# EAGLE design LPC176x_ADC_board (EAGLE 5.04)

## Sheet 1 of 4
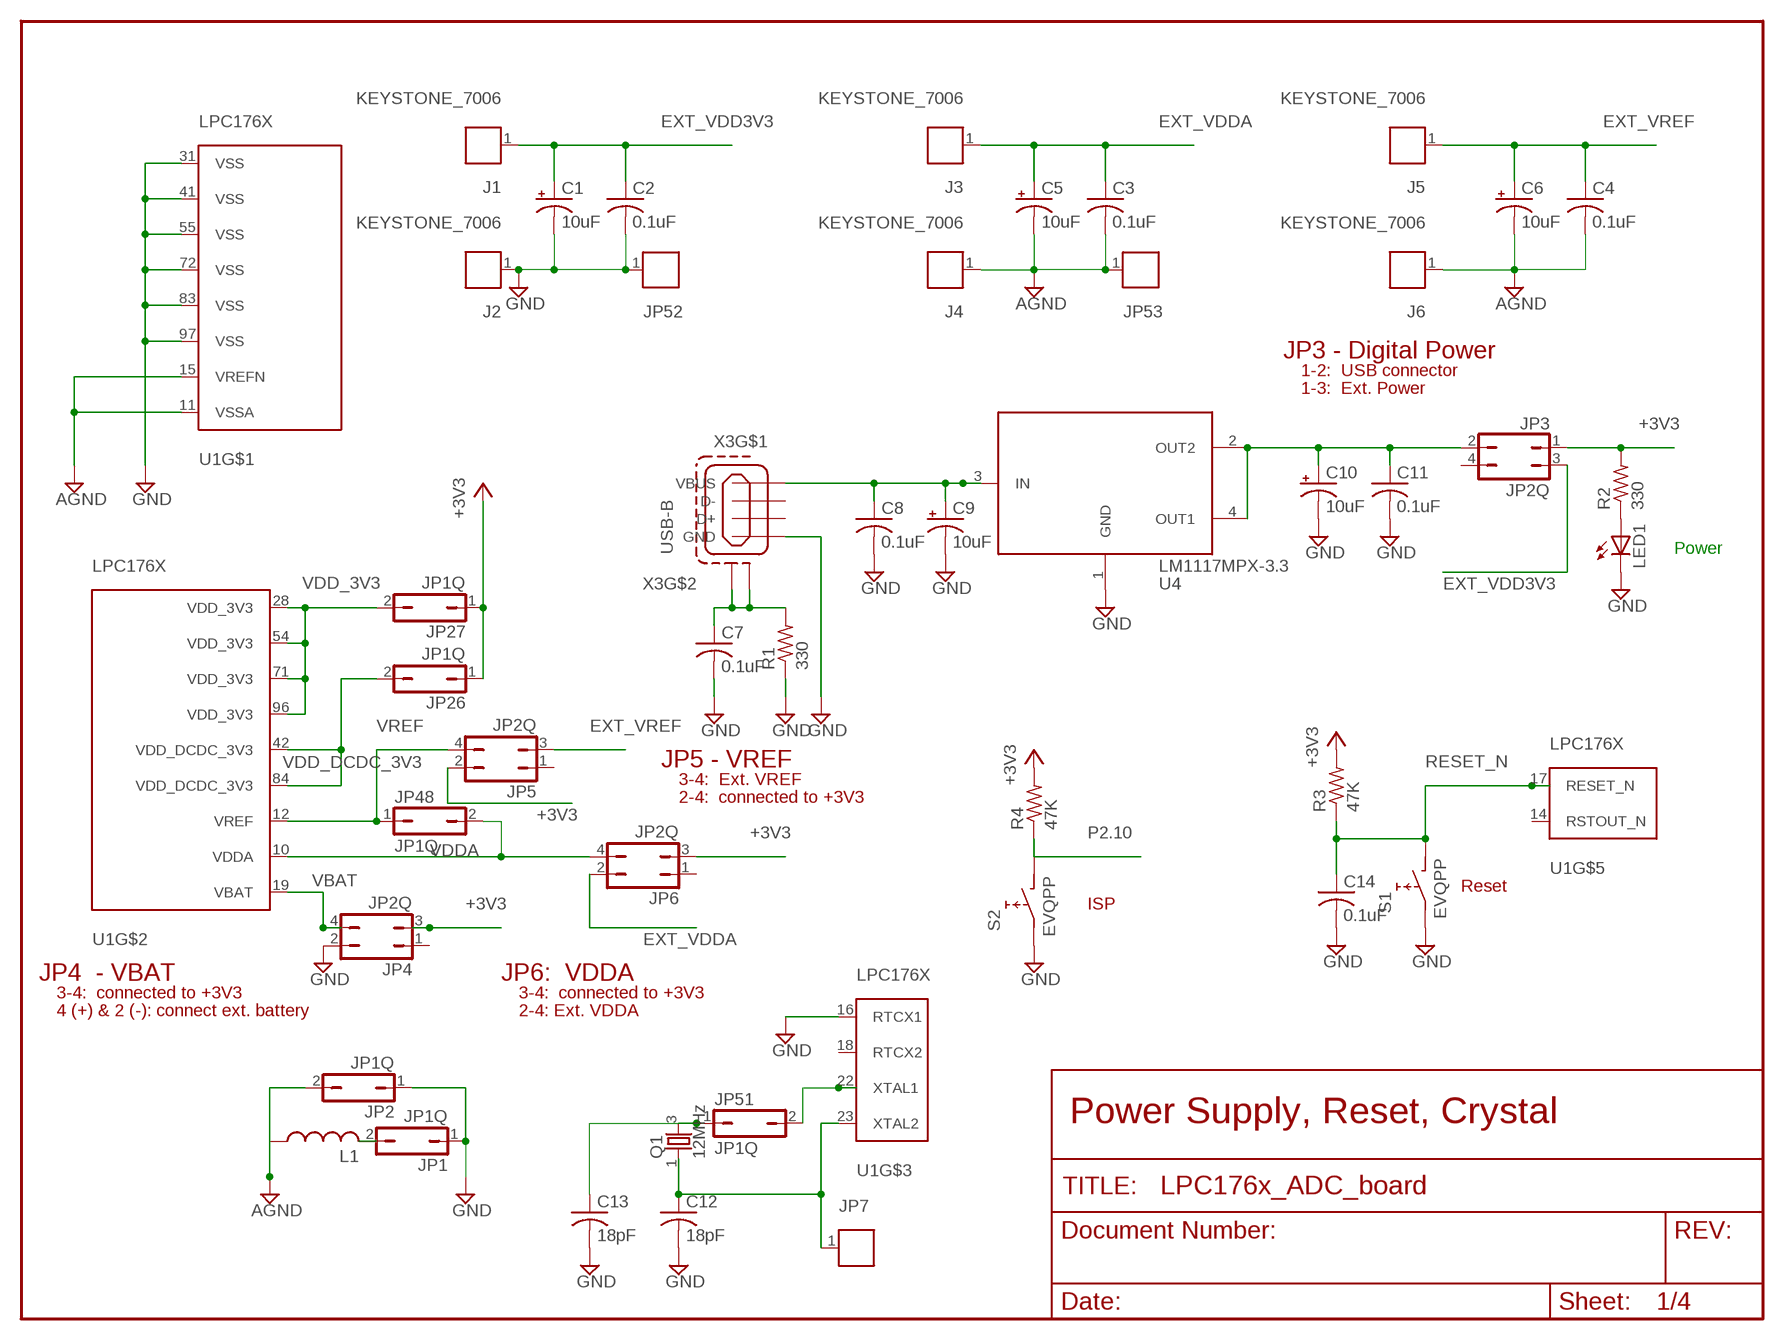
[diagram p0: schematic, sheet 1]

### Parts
C1  10uF  CPOL-USA/3216-18R  [A/3216-18R]
C2  0.1uF  C-USC0805  [C0805]
C3  0.1uF  C-USC0805  [C0805]
C4  0.1uF  C-USC0805  [C0805]
C5  10uF  CPOL-USA/3216-18R  [A/3216-18R]
C6  10uF  CPOL-USA/3216-18R  [A/3216-18R]
C7  0.1uF  C-USC0805  [C0805]
C8  0.1uF  C-USC0805  [C0805]
C9  10uF  CPOL-USA/3216-18R  [A/3216-18R]
C10  10uF  CPOL-USA/3216-18R  [A/3216-18R]
C11  0.1uF  C-USC0805  [C0805]
C12  18pF  C-USC0603  [C0603]
C13  18pF  C-USC0603  [C0603]
C14  0.1uF  C-USC0805  [C0805]
J1  KEYSTONE_7006  [KEYSTONE_7006]
J2  KEYSTONE_7006  [KEYSTONE_7006]
J3  KEYSTONE_7006  [KEYSTONE_7006]
J4  KEYSTONE_7006  [KEYSTONE_7006]
J5  KEYSTONE_7006  [KEYSTONE_7006]
J6  KEYSTONE_7006  [KEYSTONE_7006]
JP1  JP1Q  [JP1Q]
JP2  JP1Q  [JP1Q]
JP3  JP2Q  [JP2Q]
JP4  JP2Q  [JP2Q]
JP5  JP2Q  [JP2Q]
JP6  JP2Q  [JP2Q]
JP7  1PIN  [1PIN]
JP26  JP1Q  [JP1Q]
JP27  JP1Q  [JP1Q]
JP48  JP1Q  [JP1Q]
JP51  JP1Q  [JP1Q]
JP52  1PIN  [1PIN]
JP53  1PIN  [1PIN]
L1  L-US0207/15  [0207/15]
LED1  LEDCHIP-LED0603  [CHIP-LED0603]
Q1  12MHz  ABMM  [ABMM]
R1  330  R-US_R0805  [R0805]
R2  330  R-US_R0805  [R0805]
R3  47K  R-US_R0805  [R0805]
R4  47K  R-US_R0805  [R0805]
S1  EVQPP  [EVQPP]
S2  EVQPP  [EVQPP]
U1  LPC176X  [LQFP100_SOT407_1]
U4  LM1117MPX-3.3  [SOT223]
X3  USB-B  [USB-B-H]

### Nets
+3V3: JP3.1 JP4.3 JP5.2 JP6.3 JP26.1 JP27.1 R2.2 R3.2 R4.2 ; also sheet 2,3
AGND: C3.2 C4.2 C5.- C6.- J4.1 J6.1 JP2.2 JP53.1 L1.1 U1.11(VSSA) U1.15(VREFN) ; also sheet 2,3
EXT_VDD3V3: C1.+ C2.1 J1.1 JP3.3
EXT_VDDA: C3.1 C5.+ J3.1 JP6.2
EXT_VREF: C4.1 C6.+ J5.1 JP5.3
GND: C1.- C2.2 C7.2 C8.2 C9.- C10.- C11.2 C12.2 C13.2 C14.2 J2.1 JP1.1 JP2.1 JP4.2 JP52.1 LED1.C R1.1 S1.A S2.A U1.16(RTCX1) U1.31(VSS) U1.41(VSS) U1.55(VSS) U1.72(VSS) U1.83(VSS) U1.97(VSS) U4.1(GND) X3.GND ; also sheet 2,3
N$1: JP1.2 L1.2
N$2: C8.1 C9.+ U4.3(IN) X3.VBUS
N$3: LED1.A R2.1
N$4: C7.1 R1.2 X3.P$1(S1) X3.P$2(S2)
N$5: C10.+ C11.1 JP3.2 U4.2(OUT2) U4.4(OUT1)
N$10: C13.1 JP51.1 Q1.3
N$11: C12.1 JP7.1 Q1.1 U1.23(XTAL2)
N$20: JP51.2 U1.22(XTAL1)
P2.10: R4.1 S2.B ; also sheet 4
RESET_N: C14.1 R3.1 S1.B U1.17(RESET_N) ; also sheet 2
VBAT: JP4.4 U1.19(VBAT) ; also sheet 3
VDD_3V3: JP27.2 U1.28(VDD_3V3) U1.54(VDD_3V3) U1.71(VDD_3V3) U1.96(VDD_3V3) ; also sheet 3
VDD_DCDC_3V3: JP26.2 U1.42(VDD_DCDC_3V3) U1.84(VDD_DCDC_3V3) ; also sheet 3
VDDA: JP6.4 JP48.2 U1.10(VDDA) ; also sheet 3
VREF: JP5.4 JP48.1 U1.12(VREF) ; also sheet 2,3
Unconnected: JP3.4 JP4.1 JP5.1 JP6.1 U1.14(RSTOUT_N) U1.18(RTCX2) X3.D+ X3.D-

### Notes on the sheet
- JP3 - Digital Power
- 1-2:  USB connector
- 1-3:  Ext. Power
- Power
- JP5 - VREF
- 3-4:  Ext. VREF
- 2-4:  connected to +3V3
- Reset
- ISP
- JP4  - VBAT | JP6:  VDDA
- 3-4:  connected to +3V3 | 3-4:  connected to +3V3
- 4 (+) & 2 (-): connect ext. battery | 2-4: Ext. VDDA
- Power Supply, Reset, Crystal

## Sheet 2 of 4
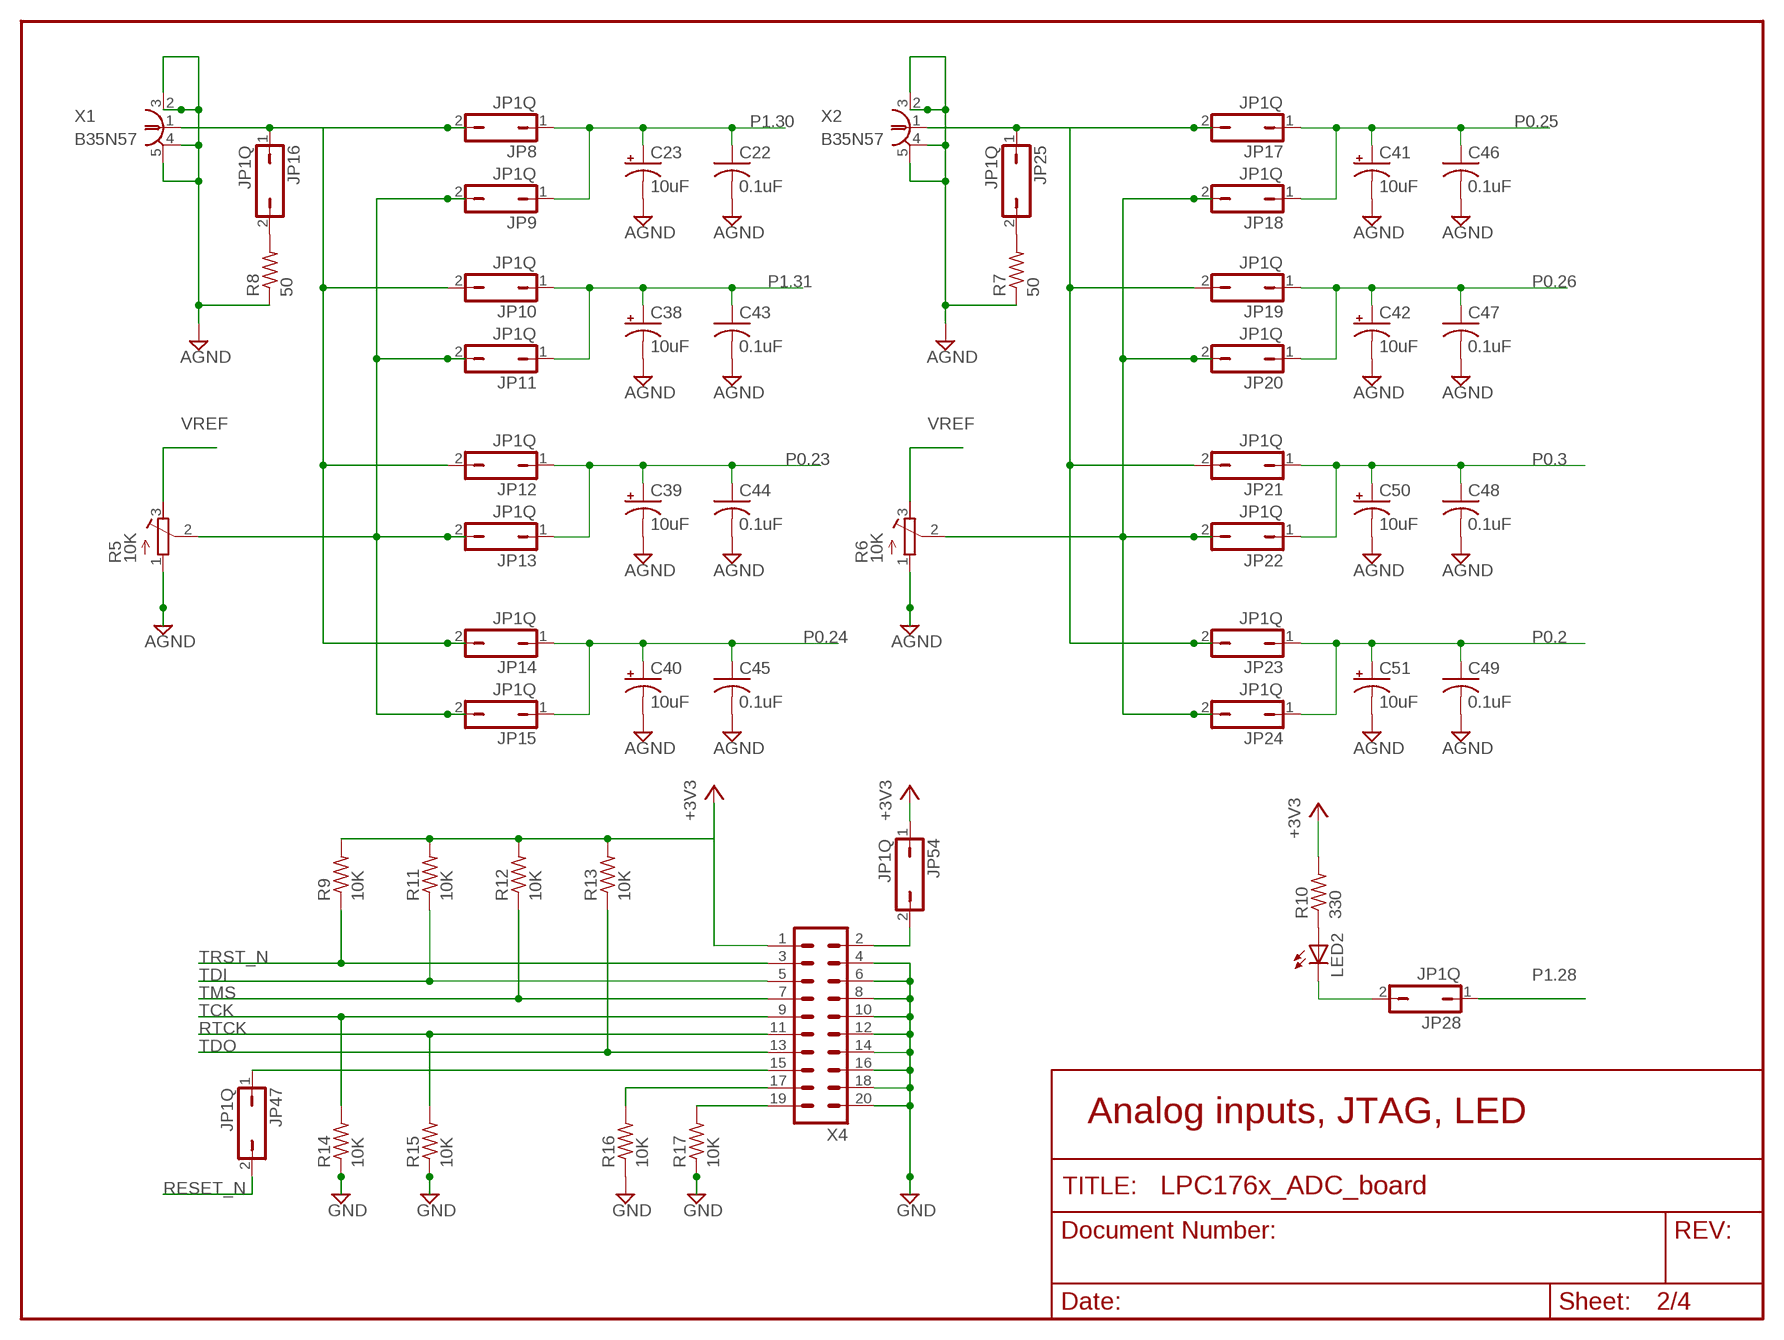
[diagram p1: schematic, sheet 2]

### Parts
C22  0.1uF  C-USC0402  [C0402]
C23  10uF  CPOL-USA/3216-18R  [A/3216-18R]
C38  10uF  CPOL-USA/3216-18R  [A/3216-18R]
C39  10uF  CPOL-USA/3216-18R  [A/3216-18R]
C40  10uF  CPOL-USA/3216-18R  [A/3216-18R]
C41  10uF  CPOL-USCT3216  [CT3216]
C42  10uF  CPOL-USCT3216  [CT3216]
C43  0.1uF  C-USC0402  [C0402]
C44  0.1uF  C-USC0402  [C0402]
C45  0.1uF  C-USC0402  [C0402]
C46  0.1uF  C-USC0402  [C0402]
C47  0.1uF  C-USC0402  [C0402]
C48  0.1uF  C-USC0402  [C0402]
C49  0.1uF  C-USC0402  [C0402]
C50  10uF  CPOL-USCT3216  [CT3216]
C51  10uF  CPOL-USCT3216  [CT3216]
JP8  JP1Q  [JP1Q]
JP9  JP1Q  [JP1Q]
JP10  JP1Q  [JP1Q]
JP11  JP1Q  [JP1Q]
JP12  JP1Q  [JP1Q]
JP13  JP1Q  [JP1Q]
JP14  JP1Q  [JP1Q]
JP15  JP1Q  [JP1Q]
JP16  JP1Q  [JP1Q]
JP17  JP1Q  [JP1Q]
JP18  JP1Q  [JP1Q]
JP19  JP1Q  [JP1Q]
JP20  JP1Q  [JP1Q]
JP21  JP1Q  [JP1Q]
JP22  JP1Q  [JP1Q]
JP23  JP1Q  [JP1Q]
JP24  JP1Q  [JP1Q]
JP25  JP1Q  [JP1Q]
JP28  JP1Q  [JP1Q]
JP47  JP1Q  [JP1Q]
JP54  JP1Q  [JP1Q]
LED2  LEDCHIP-LED0603  [CHIP-LED0603]
R5  10K  3224W3224W  [RTRIM3224W]
R6  10K  3224W3224W  [RTRIM3224W]
R7  50  R-US_R0805  [R0805]
R8  50  R-US_R0805  [R0805]
R9  10K  R-US_R0805  [R0805]
R10  330  R-US_R0805  [R0805]
R11  10K  R-US_R0805  [R0805]
R12  10K  R-US_R0805  [R0805]
R13  10K  R-US_R0805  [R0805]
R14  10K  R-US_R0805  [R0805]
R15  10K  R-US_R0805  [R0805]
R16  10K  R-US_R0805  [R0805]
R17  10K  R-US_R0805  [R0805]
X1  B35N57  [B35N57]
X2  B35N57  [B35N57]
X4  MA10-2  [MA10-2]

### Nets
+3V3: JP54.1 R9.2 R10.2 R11.2 R12.2 R13.2 X4.1 ; also sheet 1,3
AGND: C22.2 C23.- C38.- C39.- C40.- C41.- C42.- C43.2 C44.2 C45.2 C46.2 C47.2 C48.2 C49.2 C50.- C51.- R5.1(E) R6.1(E) R7.1 R8.1 X1.2 X1.3 X1.4 X1.5 X2.2 X2.3 X2.4 X2.5 ; also sheet 1,3
GND: R14.1 R15.1 R16.1 R17.1 X4.4 X4.6 X4.8 X4.10 X4.12 X4.14 X4.16 X4.18 X4.20 ; also sheet 1,3
N$7: JP16.2 R8.2
N$8: JP54.2 X4.2
N$9: JP9.2 JP11.2 JP13.2 JP15.2 R5.2(S)
N$12: R17.2 X4.19
N$13: JP8.2 JP10.2 JP12.2 JP14.2 JP16.1 X1.1
N$14: JP18.2 JP20.2 JP22.2 JP24.2 R6.2(S)
N$15: JP17.2 JP19.2 JP21.2 JP23.2 JP25.1 X2.1
N$16: JP25.2 R7.2
N$18: LED2.A R10.1
N$22: R16.2 X4.17
N$24: JP47.1 X4.15
N$51: JP28.2 LED2.C
P0.2: C49.1 C51.+ JP23.1 JP24.1 ; also sheet 3,4
P0.3: C48.1 C50.+ JP21.1 JP22.1 ; also sheet 3,4
P0.23: C39.+ C44.1 JP12.1 JP13.1 ; also sheet 4
P0.24: C40.+ C45.1 JP14.1 JP15.1 ; also sheet 4
P0.25: C41.+ C46.1 JP17.1 JP18.1 ; also sheet 4
P0.26: C42.+ C47.1 JP19.1 JP20.1 ; also sheet 4
P1.28: JP28.1 ; also sheet 4
P1.30: C22.1 C23.+ JP8.1 JP9.1 ; also sheet 4
P1.31: C38.+ C43.1 JP10.1 JP11.1 ; also sheet 4
RESET_N: JP47.2 ; also sheet 1
RTCK: R15.2 X4.11 ; also sheet 3
TCK: R14.2 X4.9 ; also sheet 3
TDI: R11.1 X4.5 ; also sheet 3
TDO: R13.1 X4.13 ; also sheet 3
TMS: R12.1 X4.7 ; also sheet 3
TRST_N: R9.1 X4.3 ; also sheet 3
VREF: R5.3(A) R6.3(A) ; also sheet 1,3

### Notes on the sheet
- Analog inputs, JTAG, LED

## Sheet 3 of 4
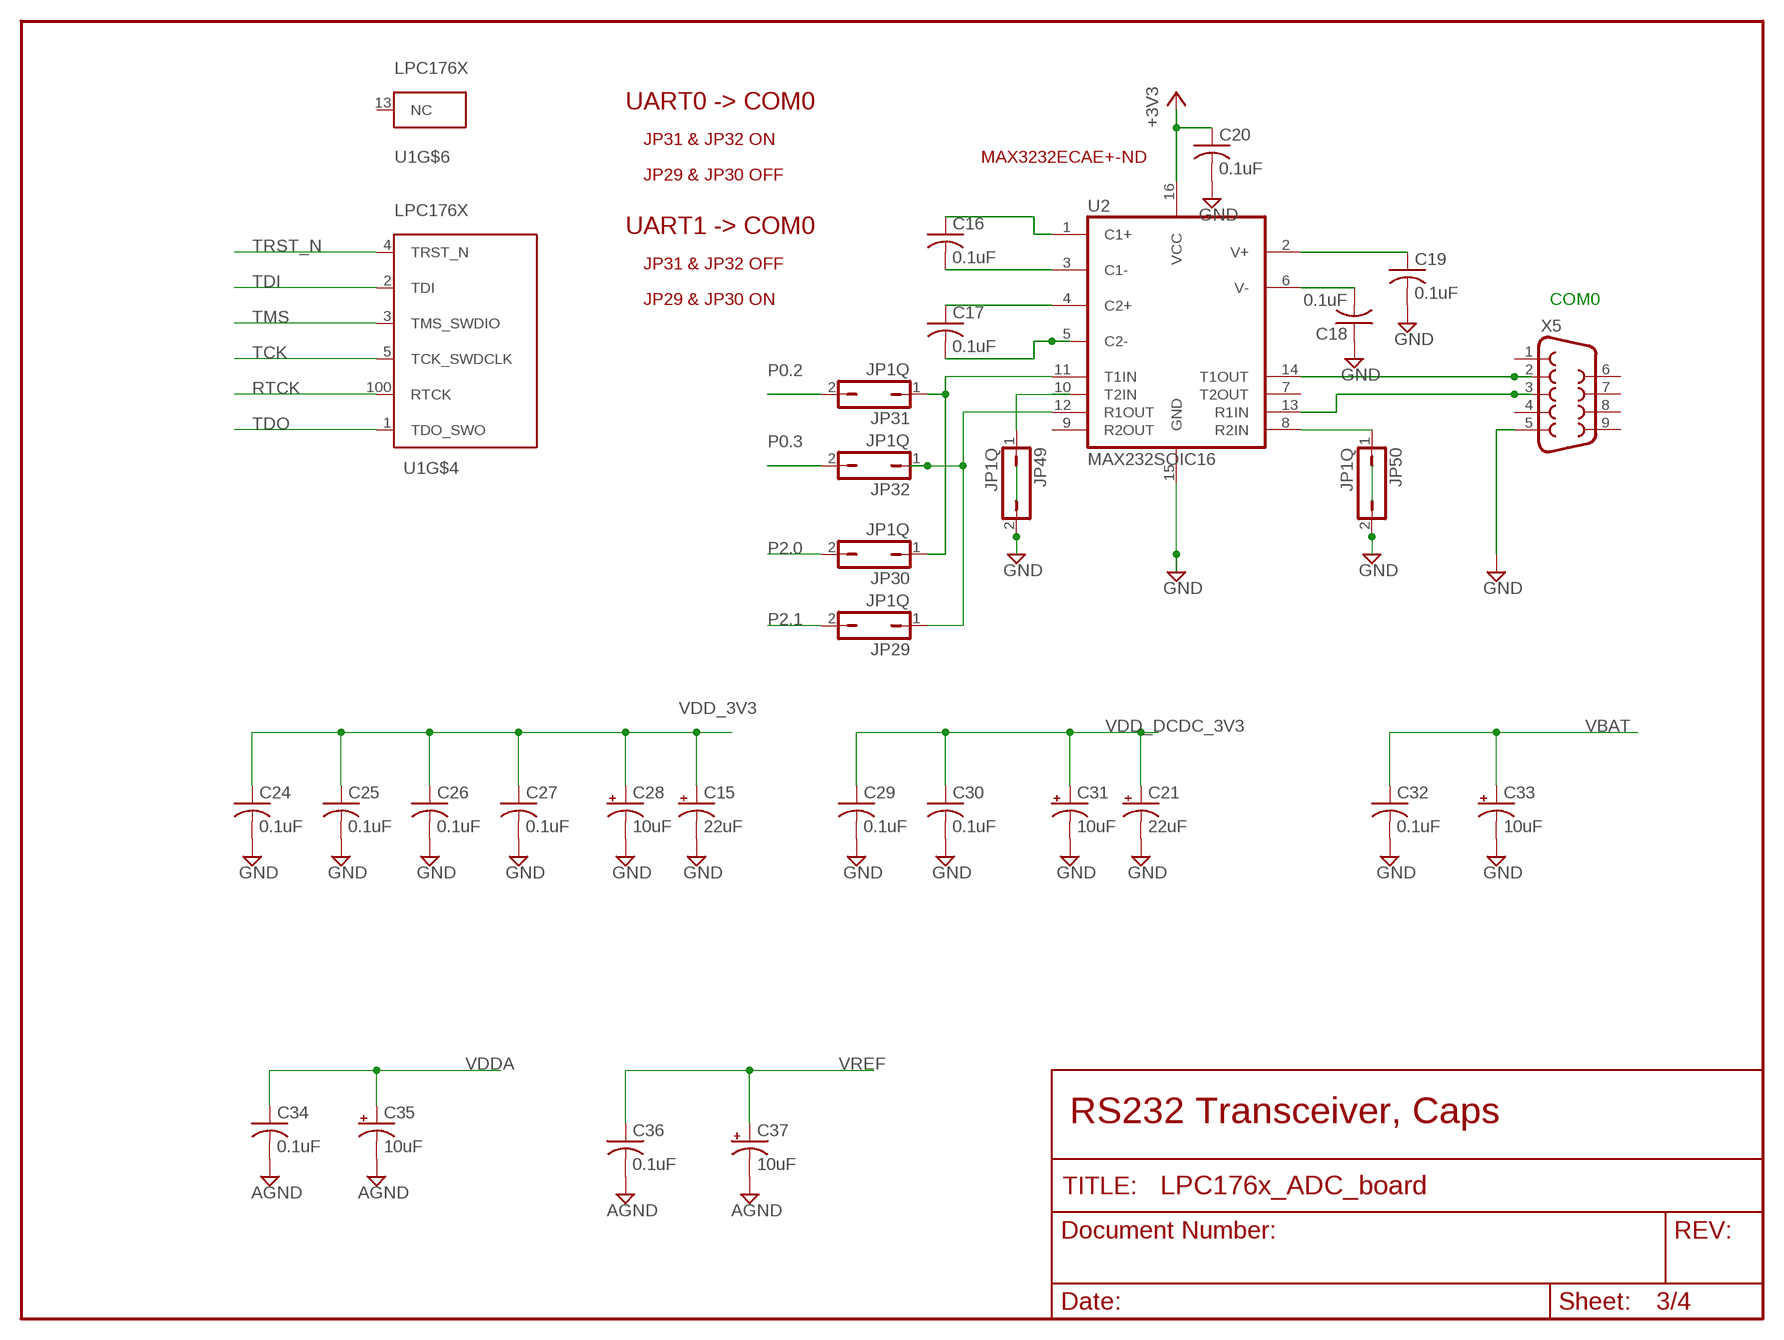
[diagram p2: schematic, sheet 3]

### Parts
C15  22uF  CPOL-USA/3216-18R  [A/3216-18R]
C16  0.1uF  C-USC0805  [C0805]
C17  0.1uF  C-USC0805  [C0805]
C18  0.1uF  C-USC0805  [C0805]
C19  0.1uF  C-USC0805  [C0805]
C20  0.1uF  C-USC0805  [C0805]
C21  22uF  CPOL-USA/3216-18R  [A/3216-18R]
C24  0.1uF  C-USC0402  [C0402]
C25  0.1uF  C-USC0402  [C0402]
C26  0.1uF  C-USC0402  [C0402]
C27  0.1uF  C-USC0402  [C0402]
C28  10uF  CPOL-USA/3216-18R  [A/3216-18R]
C29  0.1uF  C-USC0402  [C0402]
C30  0.1uF  C-USC0402  [C0402]
C31  10uF  CPOL-USA/3216-18R  [A/3216-18R]
C32  0.1uF  C-USC0402  [C0402]
C33  10uF  CPOL-USA/3216-18R  [A/3216-18R]
C34  0.1uF  C-USC0402  [C0402]
C35  10uF  CPOL-USA/3216-18R  [A/3216-18R]
C36  0.1uF  C-USC0402  [C0402]
C37  10uF  CPOL-USA/3216-18R  [A/3216-18R]
JP29  JP1Q  [JP1Q]
JP30  JP1Q  [JP1Q]
JP31  JP1Q  [JP1Q]
JP32  JP1Q  [JP1Q]
JP49  JP1Q  [JP1Q]
JP50  JP1Q  [JP1Q]
U2  MAX232SOIC16  [SO016]
X5  DB9  [DB9]

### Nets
+3V3: C20.1 U2.16(VCC) ; also sheet 1,2
AGND: C34.2 C35.- C36.2 C37.- ; also sheet 1,2
GND: C15.- C18.1 C19.2 C20.2 C21.- C24.2 C25.2 C26.2 C27.2 C28.- C29.2 C30.2 C31.- C32.2 C33.- JP49.2 JP50.2 U2.15(GND) X5.5 ; also sheet 1,2
N$6: JP30.1 JP31.1 U2.11(T1IN)
N$23: C18.2 U2.6(V-)
N$25: C19.1 U2.2(V+)
N$26: C16.1 U2.1(C1+)
N$27: C16.2 U2.3(C1-)
N$28: C17.1 U2.4(C2+)
N$29: C17.2 U2.5(C2-)
N$30: JP29.1 JP32.1 U2.12(R1OUT)
N$31: JP49.1 U2.10(T2IN)
N$32: JP50.1 U2.8(R2IN)
N$35: U2.14(T1OUT) X5.2
N$36: U2.13(R1IN) X5.3
P0.2: JP31.2 ; also sheet 2,4
P0.3: JP32.2 ; also sheet 2,4
P2.0: JP30.2 ; also sheet 4
P2.1: JP29.2 ; also sheet 4
RTCK: U1.100(RTCK) ; also sheet 2
TCK: U1.5(TCK_SWDCLK) ; also sheet 2
TDI: U1.2(TDI) ; also sheet 2
TDO: U1.1(TDO_SWO) ; also sheet 2
TMS: U1.3(TMS_SWDIO) ; also sheet 2
TRST_N: U1.4(TRST_N) ; also sheet 2
VBAT: C32.1 C33.+ ; also sheet 1
VDD_3V3: C15.+ C24.1 C25.1 C26.1 C27.1 C28.+ ; also sheet 1
VDD_DCDC_3V3: C21.+ C29.1 C30.1 C31.+ ; also sheet 1
VDDA: C34.1 C35.+ ; also sheet 1
VREF: C36.1 C37.+ ; also sheet 1,2
Unconnected: U1.13(NC) U2.7(T2OUT) U2.9(R2OUT) X5.1 X5.4 X5.6 X5.7 X5.8 X5.9

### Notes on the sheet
- UART0 -> COM0
- JP31 & JP32 ON
- MAX3232ECAE+-ND
- JP29 & JP30 OFF
- UART1 -> COM0
- JP31 & JP32 OFF
- JP29 & JP30 ON | COM0
- RS232 Transceiver, Caps

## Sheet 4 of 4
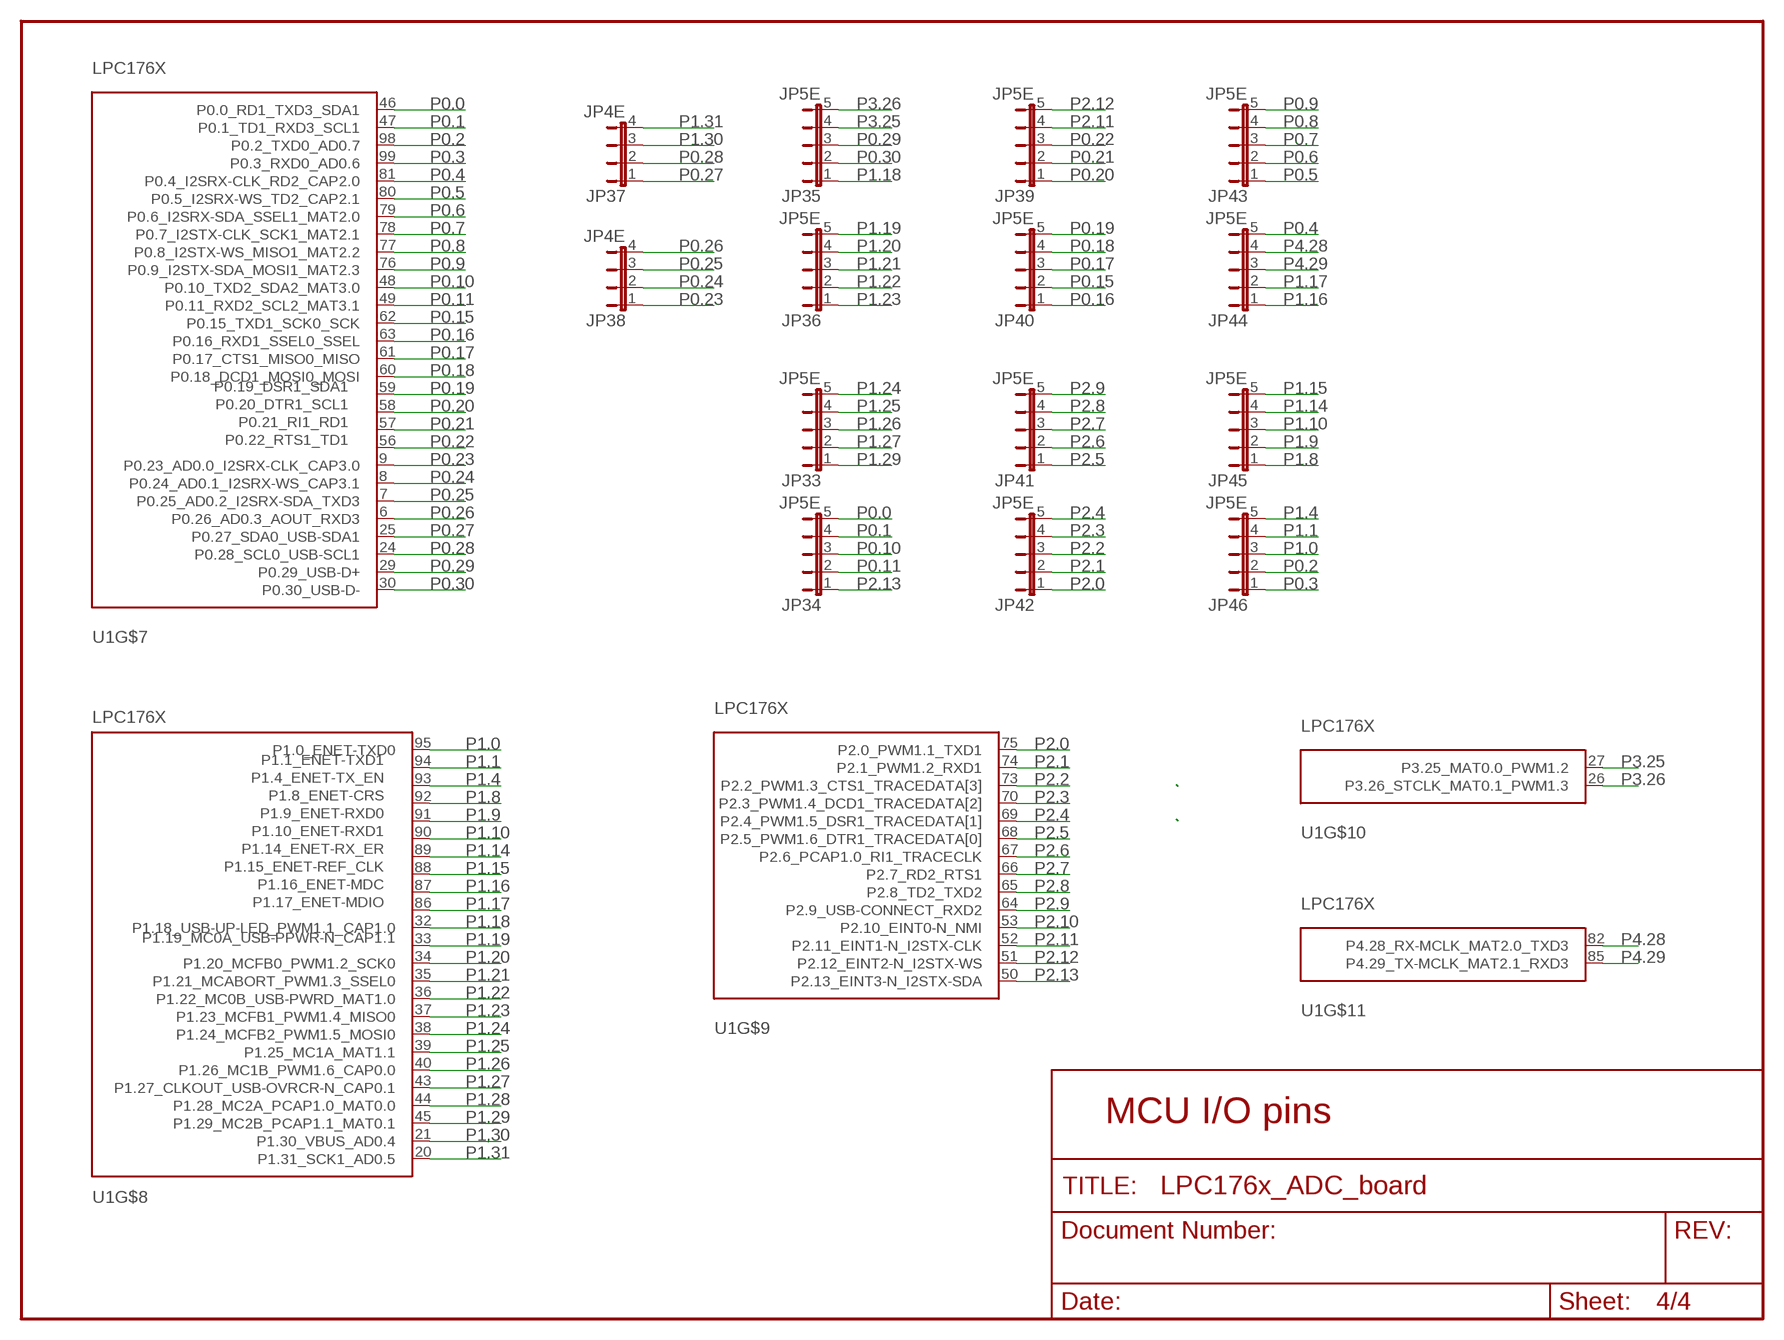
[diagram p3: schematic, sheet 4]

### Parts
JP33  JP5E  [JP5E]
JP34  JP5E  [JP5E]
JP35  JP5E  [JP5E]
JP36  JP5E  [JP5E]
JP37  JP4E  [JP4E]
JP38  JP4E  [JP4E]
JP39  JP5E  [JP5E]
JP40  JP5E  [JP5E]
JP41  JP5E  [JP5E]
JP42  JP5E  [JP5E]
JP43  JP5E  [JP5E]
JP44  JP5E  [JP5E]
JP45  JP5E  [JP5E]
JP46  JP5E  [JP5E]

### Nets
P0.0: JP34.5 U1.46(P0.0_RD1_TXD3_SDA1)
P0.1: JP34.4 U1.47(P0.1_TD1_RXD3_SCL1)
P0.2: JP46.2 U1.98(P0.2_TXD0_AD0.7) ; also sheet 2,3
P0.3: JP46.1 U1.99(P0.3_RXD0_AD0.6) ; also sheet 2,3
P0.4: JP44.5 U1.81(P0.4_I2SRX-CLK_RD2_CAP2.0)
P0.5: JP43.1 U1.80(P0.5_I2SRX-WS_TD2_CAP2.1)
P0.6: JP43.2 U1.79(P0.6_I2SRX-SDA_SSEL1_MAT2.0)
P0.7: JP43.3 U1.78(P0.7_I2STX-CLK_SCK1_MAT2.1)
P0.8: JP43.4 U1.77(P0.8_I2STX-WS_MISO1_MAT2.2)
P0.9: JP43.5 U1.76(P0.9_I2STX-SDA_MOSI1_MAT2.3)
P0.10: JP34.3 U1.48(P0.10_TXD2_SDA2_MAT3.0)
P0.11: JP34.2 U1.49(P0.11_RXD2_SCL2_MAT3.1)
P0.15: JP40.2 U1.62(P0.15_TXD1_SCK0_SCK)
P0.16: JP40.1 U1.63(P0.16_RXD1_SSEL0_SSEL)
P0.17: JP40.3 U1.61(P0.17_CTS1_MISO0_MISO)
P0.18: JP40.4 U1.60(P0.18_DCD1_MOSI0_MOSI)
P0.19: JP40.5 U1.59(P0.19_DSR1_SDA1
)
P0.20: JP39.1 U1.58(P0.20_DTR1_SCL1
)
P0.21: JP39.2 U1.57(P0.21_RI1_RD1
)
P0.22: JP39.3 U1.56(P0.22_RTS1_TD1
)
P0.23: JP38.1 U1.9(P0.23_AD0.0_I2SRX-CLK_CAP3.0) ; also sheet 2
P0.24: JP38.2 U1.8(P0.24_AD0.1_I2SRX-WS_CAP3.1) ; also sheet 2
P0.25: JP38.3 U1.7(P0.25_AD0.2_I2SRX-SDA_TXD3) ; also sheet 2
P0.26: JP38.4 U1.6(P0.26_AD0.3_AOUT_RXD3) ; also sheet 2
P0.27: JP37.1 U1.25(P0.27_SDA0_USB-SDA1)
P0.28: JP37.2 U1.24(P0.28_SCL0_USB-SCL1)
P0.29: JP35.3 U1.29(P0.29_USB-D+)
P0.30: JP35.2 U1.30(P0.30_USB-D-)
P1.0: JP46.3 U1.95(P1.0_ENET-TXD0)
P1.1: JP46.4 U1.94(P1.1_ENET-TXD1
)
P1.4: JP46.5 U1.93(P1.4_ENET-TX_EN
)
P1.8: JP45.1 U1.92(P1.8_ENET-CRS
)
P1.9: JP45.2 U1.91(P1.9_ENET-RXD0
)
P1.10: JP45.3 U1.90(P1.10_ENET-RXD1
)
P1.14: JP45.4 U1.89(P1.14_ENET-RX_ER
)
P1.15: JP45.5 U1.88(P1.15_ENET-REF_CLK
)
P1.16: JP44.1 U1.87(P1.16_ENET-MDC
)
P1.17: JP44.2 U1.86(P1.17_ENET-MDIO
)
P1.18: JP35.1 U1.32(P1.18_USB-UP-LED_PWM1.1_CAP1.0)
P1.19: JP36.5 U1.33(P1.19_MC0A_USB-PPWR-N_CAP1.1
)
P1.20: JP36.4 U1.34(P1.20_MCFB0_PWM1.2_SCK0)
P1.21: JP36.3 U1.35(P1.21_MCABORT_PWM1.3_SSEL0)
P1.22: JP36.2 U1.36(P1.22_MC0B_USB-PWRD_MAT1.0)
P1.23: JP36.1 U1.37(P1.23_MCFB1_PWM1.4_MISO0)
P1.24: JP33.5 U1.38(P1.24_MCFB2_PWM1.5_MOSI0)
P1.25: JP33.4 U1.39(P1.25_MC1A_MAT1.1)
P1.26: JP33.3 U1.40(P1.26_MC1B_PWM1.6_CAP0.0)
P1.27: JP33.2 U1.43(P1.27_CLKOUT_USB-OVRCR-N_CAP0.1)
P1.28: U1.44(P1.28_MC2A_PCAP1.0_MAT0.0) ; also sheet 2
P1.29: JP33.1 U1.45(P1.29_MC2B_PCAP1.1_MAT0.1)
P1.30: JP37.3 U1.21(P1.30_VBUS_AD0.4) ; also sheet 2
P1.31: JP37.4 U1.20(P1.31_SCK1_AD0.5) ; also sheet 2
P2.0: JP42.1 U1.75(P2.0_PWM1.1_TXD1) ; also sheet 3
P2.1: JP42.2 U1.74(P2.1_PWM1.2_RXD1) ; also sheet 3
P2.2: JP42.3 U1.73(P2.2_PWM1.3_CTS1_TRACEDATA[3])
P2.3: JP42.4 U1.70(P2.3_PWM1.4_DCD1_TRACEDATA[2])
P2.4: JP42.5 U1.69(P2.4_PWM1.5_DSR1_TRACEDATA[1])
P2.5: JP41.1 U1.68(P2.5_PWM1.6_DTR1_TRACEDATA[0])
P2.6: JP41.2 U1.67(P2.6_PCAP1.0_RI1_TRACECLK)
P2.7: JP41.3 U1.66(P2.7_RD2_RTS1)
P2.8: JP41.4 U1.65(P2.8_TD2_TXD2)
P2.9: JP41.5 U1.64(P2.9_USB-CONNECT_RXD2)
P2.10: U1.53(P2.10_EINT0-N_NMI) ; also sheet 1
P2.11: JP39.4 U1.52(P2.11_EINT1-N_I2STX-CLK)
P2.12: JP39.5 U1.51(P2.12_EINT2-N_I2STX-WS)
P2.13: JP34.1 U1.50(P2.13_EINT3-N_I2STX-SDA)
P3.25: JP35.4 U1.27(P3.25_MAT0.0_PWM1.2)
P3.26: JP35.5 U1.26(P3.26_STCLK_MAT0.1_PWM1.3)
P4.28: JP44.4 U1.82(P4.28_RX-MCLK_MAT2.0_TXD3)
P4.29: JP44.3 U1.85(P4.29_TX-MCLK_MAT2.1_RXD3)

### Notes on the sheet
- MCU I/O pins

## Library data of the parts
C1 C5 C6 C9 C10 C15 C21 C23 C28 C31 C33 C35 C37-C42 C50 C51 = rcl:CPOL-US: POLARIZED CAPACITOR, American symbol
C2-C4 C7 C8 C11-C14 C16-C20 C22 C24-C27 C29 C30 C32 C34 C36 C43-C49 = rcl:C-US: CAPACITOR, American symbol
J1-J6 = Chun:KEYSTONE_7006
JP1 JP2 JP8-JP32 JP47-JP51 JP54 = Chun:JP1Q
JP3-JP6 = Chun:JP2Q
JP7 JP52 JP53 = Chun:1PIN
JP33-JP36 JP39-JP46 = Chun:JP5E
JP37 JP38 = Chun:JP4E
L1 = rcl:L-US: INDUCTOR, American symbol
LED1 LED2 = led:LED: LED
Q1 = Chun:ABMM
R1-R4 R7-R17 = rcl:R-US_: RESISTOR, American symbol
R5 R6 = Chun:3224W: Trimm resistor
S1 S2 = Chun:EVQPP
U1 = Chun:LPC176X
U2 = SparkFun:MAX232: RS232 Transceiver Very common IC. This is generically called 'MAX232', but works with the 3V equivalent MAX3232 generic ICs. Field tested and mother approved. Spark Fun Electronics SKU : COM-00316 (DIP) and COM-00589 (SMD)
U4 = Chun:LM1117MPX-3.3
X1 X2 = Chun:B35N57
X3 = Chun:USB-B
X4 = con-lstb:MA10-2: PIN HEADER
X5 = SparkFun:DB9: DB9 Connector Standard DB9 (D-Sub 9) serial connector. Can be used for CAN bus as well as RS485 and RS232. Footprint production proven. Spark Fun Electronics SKU : PRT-00429

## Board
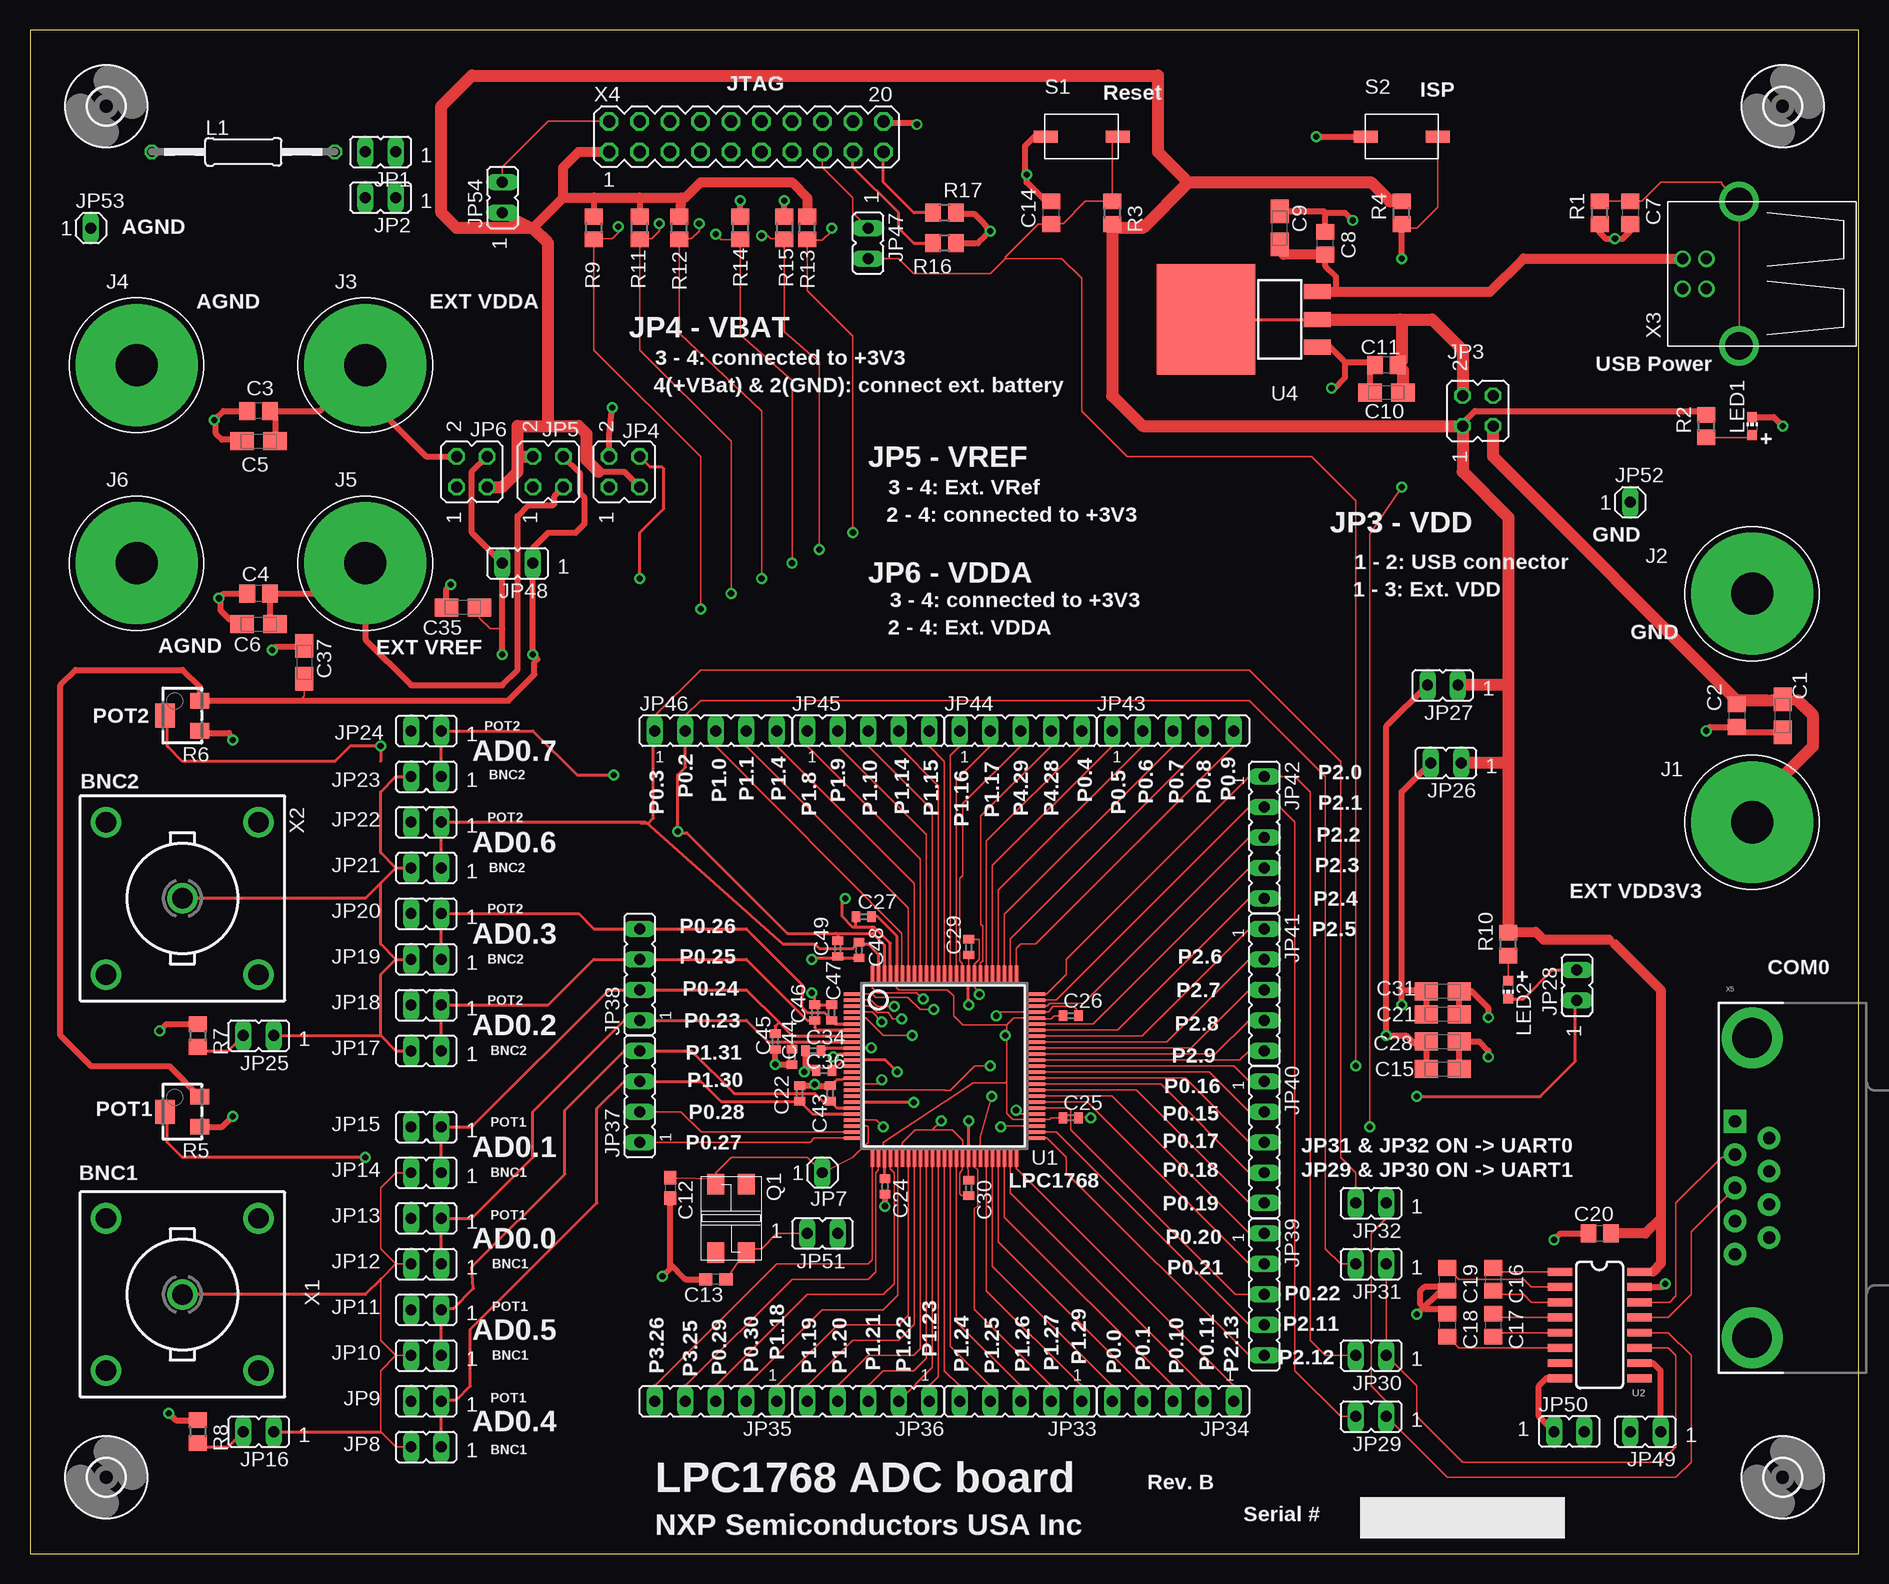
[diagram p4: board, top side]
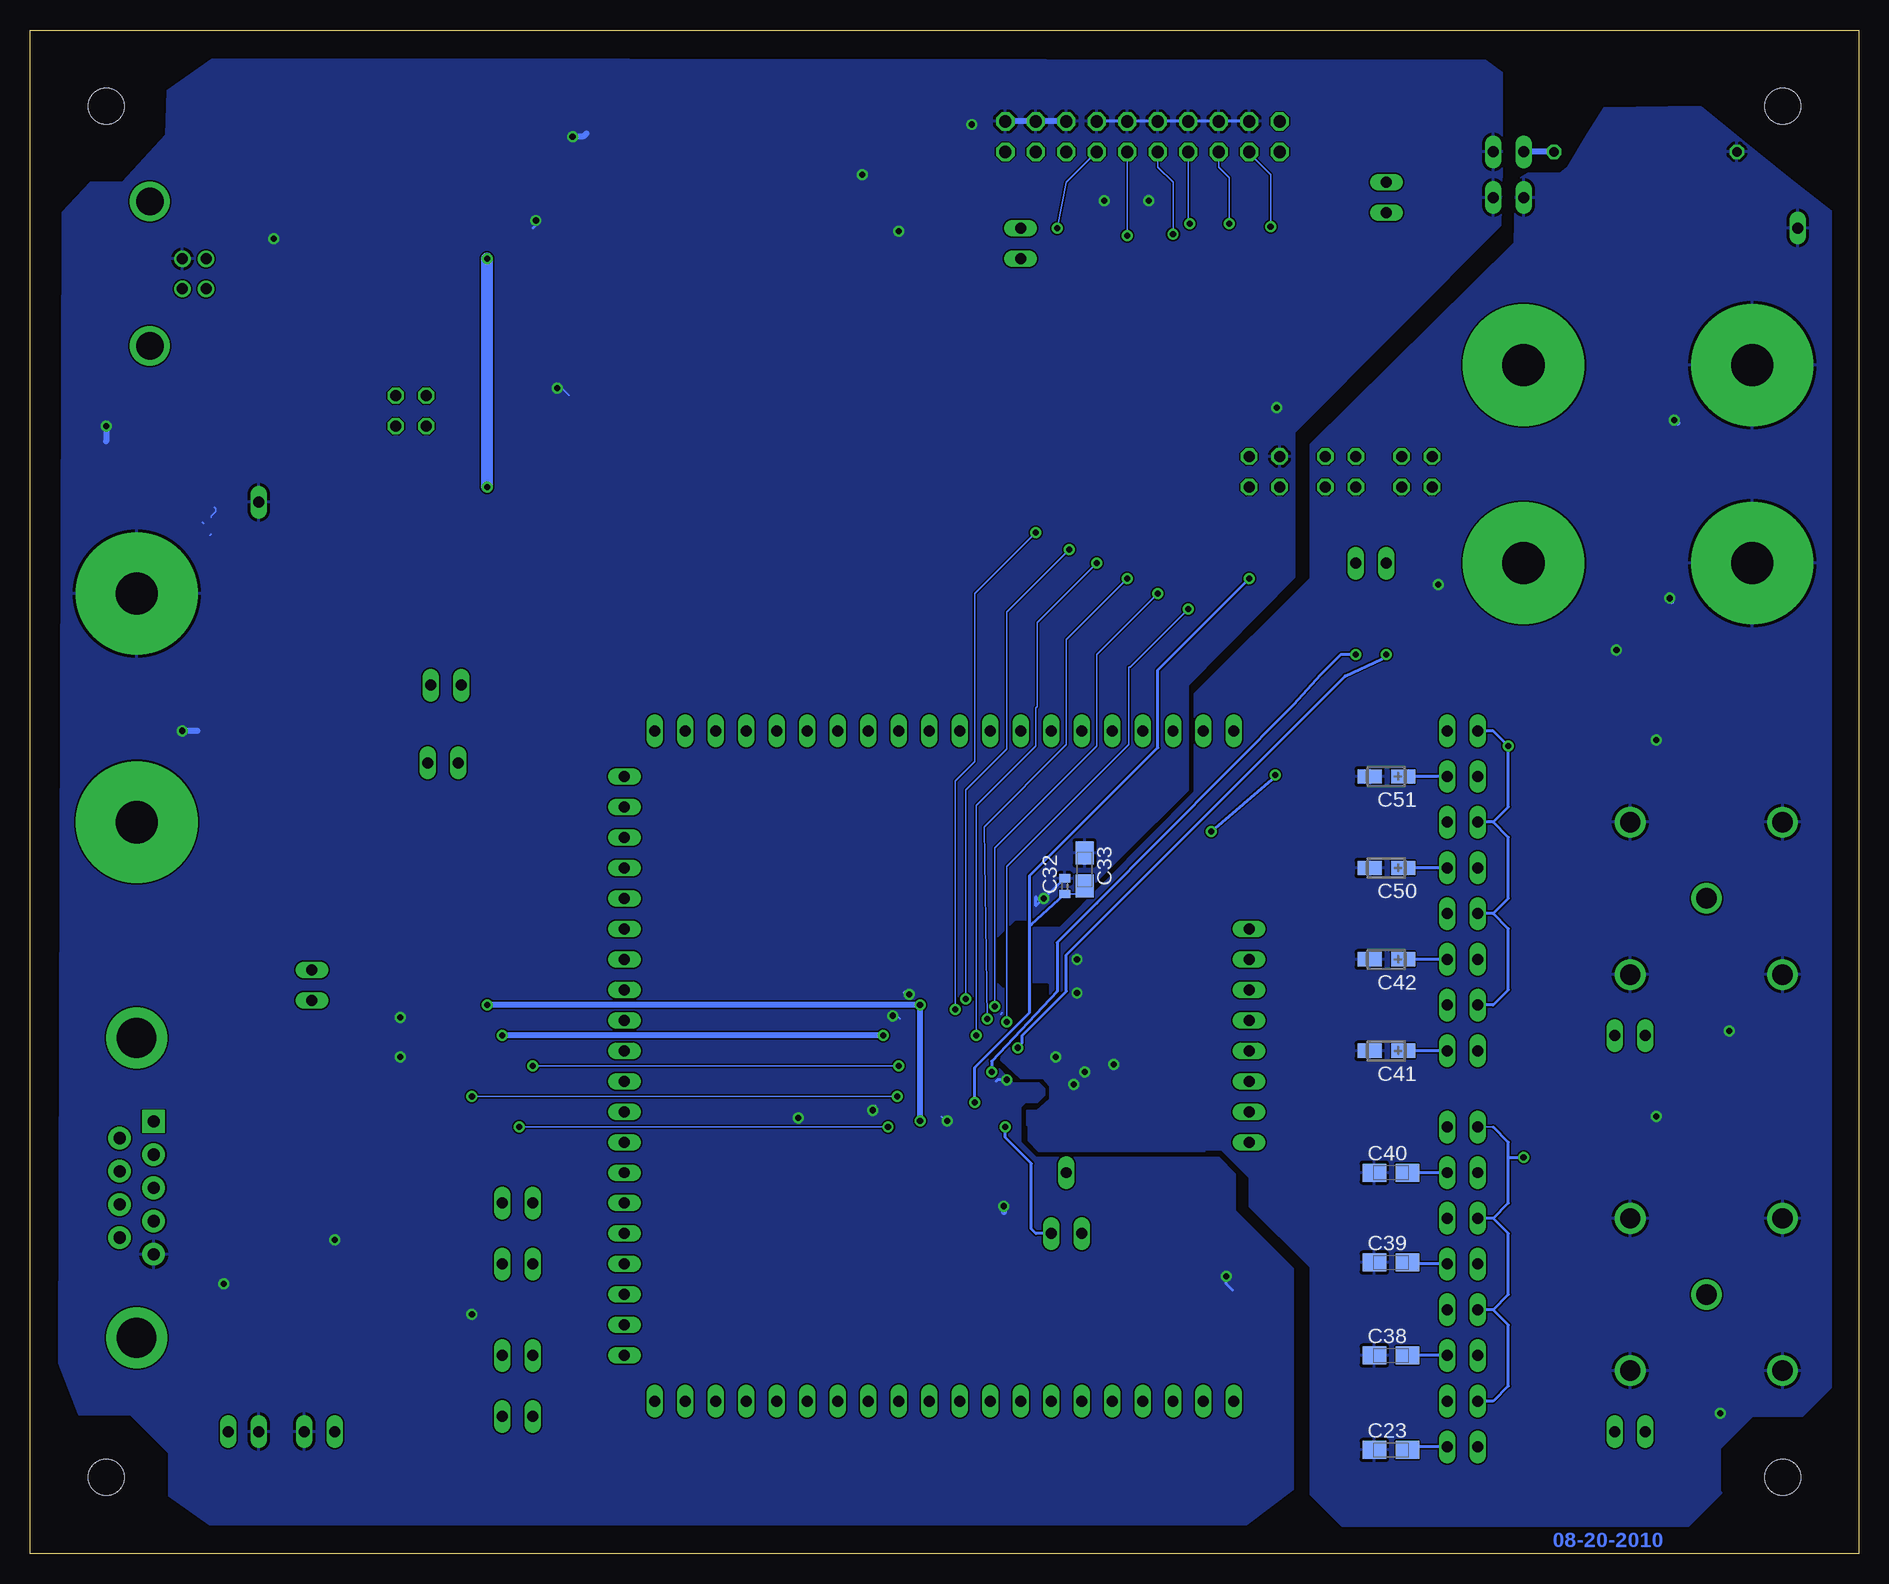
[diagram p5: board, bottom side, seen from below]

Size 152.4 x 127 mm. Coordinates in mm from the lower left corner, seen from the top.
Outline: 0,0 152.38,0 152.4,127 0,127 0,0
Copper layers (1*16): Top 0.035mm / dielectric 1.5mm / Bottom 0.035mm
Design rules "default *": minimum track width 5mil, minimum drill 10mil, track to track 5mil, track to pad 5mil, pad to pad 5mil, via to via 5mil, smd to smd 5mil, copper to edge 10mil, drill to drill 5mil, minimum pad ring 5mil, minimum via ring 8mil, stop-mask expansion 2mil, vias tented up to drill 0mil, thermal gap 10mil

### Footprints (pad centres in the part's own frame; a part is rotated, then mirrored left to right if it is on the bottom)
A/3216-18R = smd 1.95 x 1.5: + 1.375,0; - -1.375,0
C0805 = smd 1.3 x 1.5: 1 -0.95,0; 2 0.95,0
C0603 = smd 1.1 x 1: 1 -0.85,0; 2 0.85,0
C0402 = smd 0.7 x 0.9: 1 -0.65,0; 2 0.65,0
CT3216 = smd 2 x 1.2: + -1.4,0; - 1.4,0
KEYSTONE_7006 = drill 3.505 pad 10.16 round: 1 0,0
JP1Q = drill 0.914 long: 1 0,-1.27; 2 0,1.27
JP2Q = drill 0.914 octagon: 1 -1.27,-1.27; 2 -1.27,1.27; 3 1.27,-1.27; 4 1.27,1.27
1PIN = drill 0.914 long: 1 0,0
JP5E = drill 0.914 long: 1 -5.08,0; 2 -2.54,0; 3 0,0; 4 2.54,0; 5 5.08,0
JP4E = drill 0.914 long: 1 -3.81,0; 2 -1.27,0; 3 1.27,0; 4 3.81,0
0207/15 = drill 0.813 octagon: 1 -7.62,0; 2 7.62,0
CHIP-LED0603 = smd 0.8 x 0.8: A 0,-0.75; C 0,0.75
ABMM = smd 1.7 x 1.4: 1 -2.85,-1.27; 2 2.85,-1.27; 3 2.85,1.27; 4 -2.85,1.27
R0805 = smd 1.3 x 1.5: 1 -0.95,0; 2 0.95,0
RTRIM3224W = smd 1.3 x 1.6: 1 -1.25,-1.45; 3 1.25,-1.45 | smd 2 x 1.6: 2 0,1.45
EVQPP = smd 2 x 1: A -3,0; B 3,0
LQFP100_SOT407_1 = smd 0.3 x 1.6: 1 -6,-7.6; 2 -5.5,-7.6; 3 -5,-7.6; 4 -4.5,-7.6; 5 -4,-7.6; 6 -3.5,-7.6; 7 -3,-7.6; 8 -2.5,-7.6; 9 -2,-7.6; 10 -1.5,-7.6; 11 -1,-7.6; 12 -0.5,-7.6; 13 0,-7.6; 14 0.5,-7.6; 15 1,-7.6; 16 1.5,-7.6; 17 2,-7.6; 18 2.5,-7.6; 19 3,-7.6; 20 3.5,-7.6; 21 4,-7.6; 22 4.5,-7.6; 23 5,-7.6; 24 5.5,-7.6; 25 6,-7.6; 51 6,7.6; 52 5.5,7.6; 53 5,7.6; 54 4.5,7.6; 55 4,7.6; 56 3.5,7.6; 57 3,7.6; 58 2.5,7.6; 59 2,7.6; 60 1.5,7.6; 61 1,7.6; 62 0.5,7.6; 63 0,7.6; 64 -0.5,7.6; 65 -1,7.6; 66 -1.5,7.6; 67 -2,7.6; 68 -2.5,7.6; 69 -3,7.6; 70 -3.5,7.6; 71 -4,7.6; 72 -4.5,7.6; 73 -5,7.6; 74 -5.5,7.6; 75 -6,7.6 | smd 1.6 x 0.3: 26 7.6,-6; 27 7.6,-5.5; 28 7.6,-5; 29 7.6,-4.5; 30 7.6,-4; 31 7.6,-3.5; 32 7.6,-3; 33 7.6,-2.5; 34 7.6,-2; 35 7.6,-1.5; 36 7.6,-1; 37 7.6,-0.5; 38 7.6,0; 39 7.6,0.5; 40 7.6,1; 41 7.6,1.5; 42 7.6,2; 43 7.6,2.5; 44 7.6,3; 45 7.6,3.5; 46 7.6,4; 47 7.6,4.5; 48 7.6,5; 49 7.6,5.5; 50 7.6,6; 76 -7.6,6; 77 -7.6,5.5; 78 -7.6,5; 79 -7.6,4.5; 80 -7.6,4; 81 -7.6,3.5; 82 -7.6,3; 83 -7.6,2.5; 84 -7.6,2; 85 -7.6,1.5; 86 -7.6,1; 87 -7.6,0.5; 88 -7.6,0; 89 -7.6,-0.5; 90 -7.6,-1; 91 -7.6,-1.5; 92 -7.6,-2; 93 -7.6,-2.5; 94 -7.6,-3; 95 -7.6,-3.5; 96 -7.6,-4; 97 -7.6,-4.5; 98 -7.6,-5; 99 -7.6,-5.5; 100 -7.6,-6
SO016 = smd 0.66 x 2.032: 1 -4.445,-3.315; 2 -3.175,-3.315; 3 -1.905,-3.315; 4 -0.635,-3.315; 5 0.635,-3.315; 6 1.905,-3.315; 7 3.175,-3.315; 8 4.445,-3.315; 9 4.445,3.315; 10 3.175,3.315; 11 1.905,3.315; 12 0.635,3.315; 13 -0.635,3.315; 14 -1.905,3.315; 15 -3.175,3.315; 16 -4.445,3.315
SOT223 = smd 1.25 x 2.25: 1 -2.3,-3.15; 2 0,-3.15; 3 2.3,-3.15 | smd 9.2 x 8.2: 4 0,6.15
3,0 = hole 3: 0,0
B35N57 = drill 1.7 round: 1 0,0; 2 6.35,6.35; 3 -6.35,6.35; 4 -6.35,-6.35; 5 6.35,-6.35
USB-B-H = drill 0.914 round: D+ 0,1.25; D- 1.981,1.25; GND 0,-1.25; VBUS 1.981,-1.25 | drill 2.286 round: P$1 -2.718,-6.02; P$2 -2.718,6.02
MA10-2 = drill 1.016 octagon: 1 -11.43,-1.27; 2 -11.43,1.27; 3 -8.89,-1.27; 4 -8.89,1.27; 5 -6.35,-1.27; 6 -6.35,1.27; 7 -3.81,-1.27; 8 -3.81,1.27; 9 -1.27,-1.27; 10 -1.27,1.27; 11 1.27,-1.27; 12 1.27,1.27; 13 3.81,-1.27; 14 3.81,1.27; 15 6.35,-1.27; 16 6.35,1.27; 17 8.89,-1.27; 18 8.89,1.27; 19 11.43,-1.27; 20 11.43,1.27
DB9 = drill 1.016 pad 1.88 square: 1 -5.54,-1.42 | drill 1.016 pad 1.88 round: 2 -2.77,-1.42; 3 0,-1.42; 4 2.77,-1.42; 5 5.54,-1.42; 6 -4.15,1.42; 7 -1.38,1.42; 8 1.38,1.42; 9 4.15,1.42 | drill 3.302 pad 5.08 round: G1 -12.5,0; G2 12.5,0

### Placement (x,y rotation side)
C1  146.05,69.85 90 top
C2  142.24,69.85 270 top
C3  19.05,95.25 180 top
C4  19.05,80.01 180 top
C5  19.05,92.71 0 top
C6  19.05,77.47 0 top
C7  133.35,111.76 270 top
C8  107.95,109.22 90 top
C9  104.14,110.49 270 top
C10  113.03,96.77 0 top
C11  113.03,99.06 180 top
C12  53.34,30.48 270 top
C13  57.15,22.86 180 top
C14  85.09,111.76 90 top
C15  117.73,40.39 180 top
C16  121.92,22.86 270 top
C17  121.92,19.05 270 top
C18  118.11,19.05 270 top
C19  118.11,22.86 270 top
C20  130.81,26.67 180 top
C21  117.73,44.96 180 top
C22  64.14,38.35 90 top
C23  38.99,8.64 0 bottom
C24  71.25,30.61 270 top
C25  86.74,36.32 0 top
C26  86.74,44.83 0 top
C27  69.47,53.09 180 top
C28  117.73,42.67 180 top
C29  78.23,50.55 90 top
C30  78.23,30.48 270 top
C31  117.73,46.86 180 top
C32  66.17,55.63 90 bottom
C33  64.52,57.02 270 bottom
C34  65.28,41.91 180 top
C35  36.07,78.87 0 top
C36  66.17,40.26 180 top
C37  22.86,74.3 270 top
C38  38.99,16.51 0 bottom
C39  38.99,24.26 0 bottom
C40  38.99,31.75 0 bottom
C41  39.37,41.91 180 bottom
C42  39.37,49.53 180 bottom
C43  66.67,38.35 90 top
C44  63.5,41.4 270 top
C45  62.1,42.67 270 top
C46  65.41,45.09 90 top
C47  66.8,45.09 90 top
C48  69.09,50.29 270 top
C49  67.31,50.42 270 top
C50  39.37,57.15 180 bottom
C51  39.37,64.77 180 bottom
J1  143.51,60.96 0 top
J2  143.51,80.01 0 top
J3  27.94,99.06 0 top
J4  8.89,99.06 0 top
J5  27.94,82.55 0 top
J6  8.89,82.55 0 top
JP1  29.21,116.84 90 top
JP2  29.21,113.03 90 top
JP3  120.65,95.25 0 top
JP4  49.53,90.17 0 top
JP5  43.18,90.17 0 top
JP6  36.83,90.17 0 top
JP7  66.04,31.75 0 top
JP8  33.02,8.89 90 top
JP9  33.02,12.7 90 top
JP10  33.02,16.51 90 top
JP11  33.02,20.32 90 top
JP12  33.02,24.13 90 top
JP13  33.02,27.94 90 top
JP14  33.02,31.75 90 top
JP15  33.02,35.56 90 top
JP16  19.05,10.16 90 top
JP17  33.02,41.91 90 top
JP18  33.02,45.72 90 top
JP19  33.02,49.53 90 top
JP20  33.02,53.34 90 top
JP21  33.02,57.15 90 top
JP22  33.02,60.96 90 top
JP23  33.02,64.77 90 top
JP24  33.02,68.58 90 top
JP25  19.05,43.18 90 top
JP26  117.98,65.91 90 top
JP27  117.73,72.39 90 top
JP28  128.91,47.37 0 top
JP29  111.76,11.43 90 top
JP30  111.76,16.51 90 top
JP31  111.76,24.13 90 top
JP32  111.76,29.21 90 top
JP33  82.55,12.7 180 top
JP34  95.25,12.7 180 top
JP35  57.15,12.7 180 top
JP36  69.85,12.7 180 top
JP37  50.8,38.1 90 top
JP38  50.8,48.26 90 top
JP39  102.87,21.59 270 top
JP40  102.87,34.29 270 top
JP41  102.87,46.99 270 top
JP42  102.87,59.69 270 top
JP43  95.25,68.58 0 top
JP44  82.55,68.58 0 top
JP45  69.85,68.58 0 top
JP46  57.15,68.58 0 top
JP47  69.85,109.22 180 top
JP48  40.64,82.55 90 top
JP49  134.62,10.16 90 top
JP50  128.27,10.16 270 top
JP51  66.04,26.67 270 top
JP52  133.35,87.63 0 top
JP53  5.08,110.49 0 top
JP54  39.37,113.03 0 top
L1  17.78,116.84 0 top
LED1  143.51,93.98 0 top
LED2  123.19,46.99 180 top
Q1  58.42,27.94 270 top
R1  130.81,111.76 90 top
R2  139.7,93.98 90 top
R3  90.17,111.76 270 top
R4  114.3,111.76 90 top
R5  12.7,36.83 90 top
R6  12.7,69.85 90 top
R7  13.97,43.18 270 top
R8  13.97,10.16 270 top
R9  46.99,110.49 90 top
R10  123.19,50.8 90 top
R11  50.8,110.49 90 top
R12  54.1,110.49 90 top
R13  64.77,110.49 90 top
R14  59.18,110.49 270 top
R15  62.87,110.49 270 top
R16  76.2,109.22 180 top
R17  76.2,111.76 180 top
S1  87.63,118.11 0 top
S2  114.3,118.11 0 top
U1  76.2,40.64 270 top
U2  130.81,19.05 270 top
U4  104.14,102.87 90 top
U$1  [3,0]  6.35,6.35 0 top
U$2  [3,0]  146.05,6.35 0 top
U$3  [3,0]  146.05,120.65 0 top
U$4  [3,0]  6.35,120.65 0 top
X1  12.7,21.59 270 top
X2  12.7,54.61 270 top
X3  139.7,106.68 180 top
X4  59.69,118.11 0 top
X5  143.51,30.48 270 top

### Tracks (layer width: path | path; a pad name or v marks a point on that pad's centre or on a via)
+3V3
  Top 0.127: 135.25,23.5 U2.16
  Top 0.508: 50.8,113.03 R11.2 | 46.99,111.76 46.99,113.03 R9.2 | 54.29,113.03 54.61,113.03 | 43.18,93.98 43.18,94.11 43.31,93.98 | 132.08,50.8 131.95,50.8 131.57,51.18 | 40.64,91.69 40.89,91.44 | 47.37,90.17 49.53,90.17 JP4.3 | JP3.1 119.38,94.23 120.4,95.25 139.38,95.25 R2.2
  Top 0.813: 135.25,23.5 135.89,24.13 135.89,27.94 | 135.89,27.94 135.89,46.99 132.08,50.8 | C20.1 134.62,26.67 135.89,27.94 | 113.35,112.71 R4.2 | 90.49,110.49 R3.2 | X4.1 45.72,116.84 44.45,115.57 44.45,113.03 | JP54.1 41.91,110.49 44.45,113.03 | 44.45,113.03 46.99,113.03 50.8,113.03 54.29,113.03 R12.2 | R13.2 64.77,113.03 63.5,114.3 55.88,114.3 54.61,113.03 | 131.57,51.18 126.11,51.18 125.48,51.82 123.26,51.82 R10.2
  Top 1.016: R3.2 90.17,96.52 92.71,93.98 JP3.1 119.38,90.17 123.19,86.36 123.19,72.39 | 113.35,112.71 111.76,114.3 96.52,114.3 | 96.52,114.3 92.71,110.49 90.49,110.49 | 96.52,114.3 93.98,116.84 93.98,123.19 36.83,123.19 34.29,120.65 34.29,111.76 35.56,110.49 41.91,110.49 43.18,109.22 43.18,94.11 | JP6.3 39.37,88.9 40.64,90.17 40.64,91.69 40.64,93.98 43.18,93.98 | 40.89,91.44 JP5.2 | 43.31,93.98 45.72,93.98 46.35,93.34 46.35,91.19 47.37,90.17 | 123.19,72.39 123.19,66.17 | 123.19,66.17 R10.2 | 123.19,72.39 JP27.1 | JP26.1 122.94,65.91 123.19,66.17
AGND  (via drill 0.51)
  Top 0.127: 14.15,68.4 R6.1 | C6.- 18.1,77.89 | C34.2 64.63,41.77 | 22.78,75.59 C37.-
  Top 0.254: C44.2 63.52,40.77 | C48.2 67.44,49.64 C49.2 67.18,49.64 65.26,49.64 v65.15,49.53 | C47.2 C46.2 65.41,46.48 v65.15,46.74 | U1.11 67.17,41.64 v66.93,41.4 | U1.15 67.31,39.51 C43.2
  Top 0.508: R7.1 11.36,44.13 v10.79,43.56 | R5.1 16.02,35.58 v16.89,36.45 | 14.15,68.4 16.56,68.4 v16.89,67.82 | R8.1 12.13,11.11 v11.56,11.68 | C35.- 34.69,80.41 v35.05,80.77 | C5.- 17.55,92.84 16,92.84 15.49,93.34 15.49,94.36 v15.37,94.49 16.13,95.25 C3.2 | 22.78,75.59 20.47,75.59 v20.19,75.31 | 63.36,40.89 C44.2 62.12,40.75 v62.1,40.77 C45.2 | C43.2 66.66,38.99 65.66,38.99 v65.41,39.12 65.17,39 C22.2 | C36.2 64.64,40.64 | 64.64,40.64 v64.52,40.13 | 64.64,40.64 64.64,41.9 C34.2 | C4.2 16.13,80.01 v15.75,79.63 15.88,79.5 15.88,78.61 16.59,77.89 18.1,77.89
  Bottom 0.254: v65.15,49.53 65.02,49.4
  Bottom 0.508: v35.05,80.77 35.18,80.9 | v20.19,75.31 20.19,75.06 | 62.1,40.51 v62.1,40.77 | v64.52,40.13 64.64,40.13 | v15.75,79.63 15.75,79.5 15.62,79.38 | v15.37,94.49 15.11,94.23
  pour Bottom: 54.48,33.53 68.33,33.53 69.22,34.42 69.22,35.69 69.34,35.69 69.34,36.96 68.45,36.96 67.44,37.85 67.44,38.99 67.94,39.62 69.85,39.62 71.5,41.15 71.37,42.04 71.37,42.42 67.44,46.48 67.44,47.5 67.69,47.62 71.12,47.62 71.37,47.88 71.37,50.93 70.1,52.2 66.55,52.2 55.37,63.5 55.37,71.63 45.72,81.28 45.72,92.46 28.7,109.22 28.57,114.43 27.56,115.06 24.89,115.06 24.26,115.57 22.61,118.36 21.21,120.52 13.21,120.65 9.78,117.86 5.71,114.55 2.29,111.89 2.29,13.84 4.7,11.43 8.89,11.43 11.56,8.76 11.56,5.21 11.43,5.08 14.22,2.29 43.05,2.29 45.72,4.95 45.72,23.88 50.8,28.96 50.8,31.37 53.09,33.66 54.74,33.66
EXT_VDD3V3
  Top 0.254: 142.24,71.12 C2.1 | 144.78,71.12 144.68,71.12
  Top 0.813: 147.32,71.12 144.78,71.12
  Top 1.016: JP3.3 121.92,91.44 142.24,71.12 144.68,71.12 C1.+ | J1.1 143.51,62.23 148.59,67.31 148.59,69.85 147.32,71.12
EXT_VDDA
  Top 0.508: JP6.2 33.02,91.44 27.94,96.52 J3.1 24.13,95.25 C3.1 20.43,94.83 C5.+
EXT_VREF
  Top 0.508: C6.+ 20,77.89 C4.1 25.4,80.01 J5.1 27.94,76.2 31.75,72.39 39.37,72.39 40.64,73.66 40.64,86.49 41.53,87.38 43.56,87.38 43.69,87.5 43.69,88.14 JP5.3
GND  (via drill 0.51)
  Top 0.127: U1.16 70.64,39.14 v70.99,39.5 | 73.79,35.31 72.7,34.22 U1.31 72.64,32.98 | 73.79,35.31 76.83,35.31 77.72,34.42 77.72,33.06 U1.41 77.7,31.98 77.47,31.75 77.47,29.97 77.6,29.84 78.09,29.84 C30.2 | 73.79,35.31 75.18,35.31 v75.95,36.07 | U1.55 82.49,36.64 v82.17,36.96 | v79.12,46.61 78.7,47.28 U1.83 78.7,49.11 79.12,49.53 79.12,51.18 78.74,51.18 78.25,51.05 C29.2 | v80.52,44.83 80.83,45.14 U1.72 84.89,45.14 85.22,45.59 87,45.59 87.25,45.34 87.25,44.97 C26.2 | 108.34,100.57 U4.1 | v108.46,97.16 108.58,97.03 | 117.73,20.38 C18.1 | C25.2 88.27,36.45 v88.39,36.32
  Top 0.254: v139.7,68.58 140.02,68.9 | 107.95,111.76 107.84,111.86 | 111.83,99.31 C11.2 111.63,98.61 111.63,98.55 111.66,98.53 | X4.20 71.25,119.25 | C12.2 53.34,24.13 | X3.GND 139.83,108.06 | C28.- 120.14,42.67 | C31.- 119.89,46.86 | U1.97 71.7,50.85 70.36,52.2 68.71,52.2 | 68.71,52.2 68.58,52.2 67.69,53.09 67.69,54.38 v67.92,54.61 | C27.2 68.82,52.31 68.71,52.2 | 78.74,109.22 78.99,109.22 | 77.28,111.63 R17.1 | 79.63,109.86 79.76,109.98
  Top 0.508: 109.6,99.31 108.34,100.57 | 109.6,99.31 109.6,98.04 108.58,97.03 | C1.- 142.66,68.47 C2.2 140.02,68.9 | LED1.C 145.3,94.73 v146.05,93.98 | 107.84,111.86 C9.- | C8.2 107.95,111.76 109.6,111.76 v110.24,111.12 | 109.6,99.31 111.83,99.31 | 111.66,98.53 C10.- | v107.19,118.11 S2.A | 53.34,24.13 54.61,22.86 C13.2 | C12.2 53.34,23.75 v52.7,23.11 | U2.15 136.02,22.23 v136.27,22.48 | JP4.2 48.26,93.22 v48.51,95.5 | 117.73,21.59 118.05,21.91 C19.2 117.8,22.23 | C21.- C31.- | C15.- C28.- 120.78,42.67 121.54,41.91 v121.54,41.4 | 71.25,119.25 73.79,119.25 v73.91,119.13 | C14.2 84.65,112.71 83.06,114.3 v83.06,114.94 82.93,115.06 82.93,117.35 83.69,118.11 S1.A | 133.22,110.68 C7.2 133.35,110.24 132.72,109.6 v132.08,109.6 131.83,109.6 | R14.1 v59.18,112.78 | R15.1 v62.87,112.78 | R1.1 130.81,110.11 131.32,109.6 131.83,109.6 | 131.83,109.6 131.95,109.6 | C24.2 v71.25,28.96 | 119.89,46.86 120.14,46.86 121.54,45.47 v121.54,44.7 | 117.73,20.38 116.27,20.38 115.82,20.83 115.82,21.84 116.2,22.23 117.8,22.23 | 117.8,22.23 117.8,22.16 v115.57,19.94 | C20.2 127.51,26.67 v127,26.16 | R16.1 78.74,109.22 | 78.99,109.22 79.63,109.86 | 77.28,111.63 78.74,111.63 79.38,111 v80.01,110.24 79.76,109.98
  Bottom 0.127: v75.95,36.07 76.07,36.07 76.45,36.45 | v82.17,36.96 82.17,37.08 81.92,37.34 | v79.12,46.61 79.5,46.86 79.63,46.74 | v80.52,44.83 80.14,44.83 79.88,44.58 | 71.5,44.96 71.37,45.09 | v108.46,97.16 108.08,97.16 107.44,96.52 | 137.92,85.85 138.05,85.98 | 137.29,84.96 137.41,84.84 | 137.29,86.36 137.29,86.49 136.91,86.87 136.91,87.12 137.03,87.25 | v136.27,22.48 136.27,22.61 | v48.51,95.5 48.26,95.76 | v88.39,36.32 88.52,36.2
  Bottom 0.254: v110.24,111.12 110.24,110.74 110.49,110.49 | X4.4 X4.6 X4.8 X4.10 X4.12 X4.14 | v52.7,23.11 52.7,22.48 52.2,21.97 | 68.33,54.48 68.58,54.74 68.58,53.99 v67.92,54.61 | v67.92,54.61 67.8,54.73 | 67.8,54.73 C32.2 | v70.99,39.5 71.75,39.5 71.88,39.37 | v67.92,54.61 67.92,54.61 67.8,54.73 | v80.01,110.24 80.26,110.24
  Bottom 0.508: 138.43,68.58 v139.7,68.58 | v146.05,93.98 146.05,92.71 | v107.19,118.11 106.3,118.11 106.05,118.36 | v73.91,119.13 74.04,119.13 | v83.06,114.94 82.93,114.94 82.8,115.06 | v59.18,112.78 59.18,113.03 | v62.87,112.78 62.87,112.9 | v71.25,28.96 71.25,28.45 | v121.54,44.7 121.54,44.58 | v121.54,41.4 121.54,41.27 | v115.57,19.94 115.44,19.81 | v127,26.16 127,26.29 | X4.20 X4.18 X4.16
  pour Bottom: 53.34,33.02 68.58,33.02 69.85,34.29 69.85,37.21 69.47,37.59 68.45,37.59 67.82,38.23 67.82,38.73 68.33,39.24 70.48,39.24 72.14,40.89 72.14,42.29 67.94,46.48 67.94,46.86 68.2,47.12 71.37,47.12 71.88,47.62 71.88,51.31 70.36,52.83 66.8,52.83 55.88,63.63 55.88,72.39 46.99,81.41 46.99,93.47 29.84,110.74 29.72,115.44 29.72,123.44 31.11,124.46 33.02,124.46 137.16,124.59 140.97,121.92 141.1,118.24 144.65,114.3 147.32,114.3 149.73,111.76 149.99,15.88 148.34,11.56 144.02,11.56 140.84,8.38 140.84,4.83 137.41,2.41 51.05,2.41 47.12,5.33 47.12,23.75 51.94,28.57 51.94,31.62
N$1
  Bottom 0.508: L1.2 JP1.2
N$2
  Top 0.127: 104.46,108.27 104.46,108.8 C9.+
  Top 0.508: C8.1 107.95,107.31 108.84,106.43 108.84,105.17
  Top 0.813: U4.3 108.84,105.17 121.68,105.17 124.46,107.95 137.7,107.95 X3.VBUS | C8.1 104.46,108.27
N$3
  Top 0.127: R2.1 143.31,93.03 LED1.A
N$4
  Top 0.127: R1.2 C7.1 134.3,112.71 135.89,114.3 140.97,114.3 140.97,114.15 X3.P$1 X3.P$2
N$5
  Top 0.254: 114.32,99.4 C11.1 | U4.4 U4.2
  Top 0.508: 114.17,102.87 114.32,102.72 | C11.1 114.41,98.64
  Top 1.016: JP3.2 119.38,100.33 116.84,102.87 114.17,102.87 U4.2 | 114.32,102.72 114.32,99.4 | 114.41,98.64 C10.+
N$6
  Top 0.127: U2.11 136.53,17.14 137.16,16.51 137.16,8.89 135.89,7.62 119.38,7.62 115.57,11.43 115.57,13.97 JP30.1 JP31.1
N$7
  Top 0.254: JP16.2 16.51,8.89 14.29,8.89 R8.2
N$8
  Top 0.127: X4.2 43.18,119.38 39.37,115.57 JP54.2
N$9  (via drill 0.51)
  Top 0.254: v27.94,33.02 12.7,33.02 11.43,34.29 11.43,36.65 R5.2
  Bottom 0.127: 30.48,35.56 JP15.2
  Bottom 0.254: JP9.2 30.48,12.7 29.21,13.97 29.21,19.05 30.48,20.32 | 30.48,20.32 JP11.2 | 30.48,20.32 29.21,21.59 29.21,26.67 30.48,27.94 | 30.48,27.94 JP13.2 | 30.48,27.94 29.21,29.21 29.21,33.02 | 30.48,35.56 29.21,34.29 29.21,33.02 | 29.21,33.02 v27.94,33.02
N$10
  Top 0.127: C13.1 59.27,24.67 Q1.3 60,25.4 60.96,25.4 62.23,26.67 JP51.1
N$11
  Top 0.127: U1.23 69.77,35.64 69.85,35.56 69.85,34.29 68.58,33.02 JP7.1 64.77,33.02 58.42,33.02 57.15,31.75 Q1.1 57.57,31.21 C12.1
N$12
  Top 0.254: R17.2 73.66,111.76 71.12,114.3 X4.19
N$13
  Top 0.127: 30.48,24.13 29.21,22.86 29.21,17.78 30.48,16.51 | 30.48,16.51 JP10.2 | 30.48,24.13 JP12.2 | 30.48,24.13 29.21,25.4 29.21,30.48 30.48,31.75 JP14.2 | JP8.2 30.48,8.89 29.21,10.16 29.21,15.24 30.48,16.51
  Top 0.254: X1.1 27.94,21.59 29.21,22.86 | JP16.1 29.21,10.16
N$14  (via drill 0.51)
  Top 0.254: 29.21,66.04 v29.21,67.31 26.67,67.31 25.4,66.04 12.7,66.04 11.43,67.31 11.43,69.67 R6.2
  Bottom 0.254: JP24.2 30.48,68.58 v29.21,67.31 29.21,62.23 30.48,60.96 | 30.48,60.96 JP22.2 | 30.48,60.96 29.21,59.69 29.21,54.61 30.48,53.34 | 30.48,53.34 JP20.2 | 30.48,53.34 29.21,52.07 29.21,46.99 30.48,45.72 JP18.2
N$15
  Top 0.254: JP17.2 30.48,41.91 29.21,43.18 | 29.21,43.18 29.21,48.26 30.48,49.53 | 30.48,49.53 JP19.2 | 30.48,49.53 29.21,50.8 29.21,55.88 | 29.21,55.88 30.48,57.15 | 30.48,57.15 JP21.2 | 30.48,57.15 29.21,58.42 29.21,63.5 30.48,64.77 JP23.2 | X2.1 27.94,54.61 29.21,55.88 | JP25.1 29.21,43.18
N$16
  Top 0.254: JP25.2 16.51,41.91 14.29,41.91 R7.2
N$18
  Top 0.127: LED2.A R10.1
N$20  (via drill 0.51)
  Top 0.127: U1.22 70.54,36.14 v71.12,35.56
  Bottom 0.254: JP51.2 68.58,26.67 68.96,27.05 68.96,32.51 71.12,34.67 v71.12,35.56
N$22
  Top 0.254: R16.2 73.66,109.22 72.39,110.49 72.39,111.76 68.58,115.57 X4.17
N$23
  Top 0.127: U2.6 119.06,17.14 C18.2
N$24
  Top 0.127: X4.15 66.04,115.57 68.58,113.03 68.58,111.76 JP47.1
N$25
  Top 0.127: U2.2 125.09,22.23 124.46,22.86 119.06,22.86 C19.1
N$26
  Top 0.127: U2.1 122.23,23.5 C16.1
N$27
  Top 0.127: U2.3 125.09,20.95 124.46,21.59 122.24,21.59 C16.2
N$28
  Top 0.127: U2.4 122.23,19.68 C17.1
N$29
  Top 0.127: U2.5 122.23,18.41 C17.2
N$30
  Top 0.127: U2.12 136.53,18.41 138.43,16.51 138.43,7.62 137.16,6.35 118.11,6.35 JP29.1 113.03,12.7 111.76,13.97 111.76,26.67 113.03,27.94 JP32.1
N$31
  Top 0.127: 135.25,15.88 U2.10
  Top 0.508: 135.25,15.88 135.89,15.24 JP49.1
N$32
  Top 0.127: 126.36,14.61 U2.8
  Top 0.508: 126.36,14.61 125.73,13.97 125.73,11.43 JP50.1
N$35
  Top 0.127: X5.2 141.86,33.02 140.97,33.02 137.16,29.21 137.16,21.46 136.65,20.95 U2.14
N$36
  Top 0.127: U2.13 136.53,19.68 138.43,21.59 138.43,26.82 X5.3
N$51
  Top 0.254: LED2.C 124.47,46.24 126.87,48.64 JP28.2
P0.0
  Top 0.127: JP34.5 90.17,13.97 80.2,23.94 U1.46
P0.1
  Top 0.127: U1.47 80.7,25.98 92.71,13.97 JP34.4
P0.2  (via drill 0.51)
  Top 0.127: 54.61,67.31 54.61,67.82 JP46.2 54.61,69.85 55.88,71.12 101.6,71.12 107.95,64.77 107.95,25.4 109.22,24.13 JP31.2
  Top 0.254: U1.98 71.2,50.72 70.23,51.69 67.18,51.69 | JP23.1 JP24.1 41.91,68.58 45.59,64.9 v48.64,64.9 | 67.18,51.69 63.12,51.69 54.74,60.07 54.1,60.07 v53.98,60.2 53.98,64.9 54.61,65.53 54.61,67.82 | C49.1 67.31,51.56 67.18,51.69
  Bottom 0.254: v48.64,64.9 48.64,64.77 v53.98,60.2 | JP23.1 C51.+
P0.3
  Top 0.127: 52.07,67.31 JP46.1 52.07,69.85 55.88,73.66 101.6,73.66 109.22,66.04 109.22,33.02 110.49,31.75 JP32.2 | 51.47,60.82 50.94,60.82 50.8,60.96
  Top 0.254: U1.99 70.7,49.95 69.85,50.8 69.23,50.8 C48.1 68.56,50.42 65.79,50.42 65.41,50.8 62.74,50.8 51.31,60.96 50.8,60.96 JP22.1 JP21.1 | JP46.1 51.94,68.45 51.94,61.3 51.47,60.82
  Bottom 0.254: JP21.1 C50.+
P0.4
  Top 0.127: U1.81 79.7,59.38 87.63,67.31 JP44.5
P0.5
  Top 0.127: U1.80 80.2,57.34 90.17,67.31 JP43.1
P0.6
  Top 0.127: U1.79 80.7,55.3 92.71,67.31 JP43.2
P0.7
  Top 0.127: U1.78 81.2,53.26 95.25,67.31 JP43.3
P0.8
  Top 0.127: U1.77 81.7,51.22 97.79,67.31 JP43.4
P0.9
  Top 0.127: U1.76 82.2,50.45 82.55,50.8 83.82,50.8 100.33,67.31 JP43.5
P0.10
  Top 0.127: U1.48 81.2,28.02 95.25,13.97 JP34.3
P0.11
  Top 0.127: U1.49 81.7,30.06 97.79,13.97 JP34.2
P0.15
  Top 0.127: U1.62 98.29,40.14 101.6,36.83 JP40.2
P0.16
  Top 0.127: U1.63 100.33,40.64 101.6,39.37 JP40.1
P0.17
  Top 0.127: U1.61 96.25,39.64 101.6,34.29 JP40.3
P0.18
  Top 0.127: U1.60 94.21,39.14 101.6,31.75 JP40.4
P0.19
  Top 0.127: U1.59 92.17,38.64 101.6,29.21 JP40.5
P0.20
  Top 0.127: U1.58 90.13,38.14 101.6,26.67 JP39.1
P0.21
  Top 0.127: U1.57 88.09,37.64 101.6,24.13 JP39.2
P0.22
  Top 0.127: 101.6,21.59 JP39.3 100.46,21.59 86.74,35.31 86.74,36.96 86.56,37.14 U1.56
P0.23
  Top 0.254: 63.5,42.64 61.5,42.64 59.69,44.45 JP38.1 49.53,44.45 41.91,36.83 41.91,33.02 36.83,27.94 JP13.1 JP12.1 | 63.5,42.64 U1.9 | 63.5,42.64 C44.1
  Bottom 0.254: JP12.1 37.49,24.13 C39.+
P0.24
  Top 0.254: U1.8 63.54,43.14 62.42,44.26 | 62.42,44.26 59.69,46.99 JP38.2 48.26,46.99 36.83,35.56 JP15.1 JP14.1 | C45.1 62.1,43.94 62.42,44.26
  Bottom 0.254: 37.85,31.75 C40.+ JP14.1
P0.25
  Top 0.254: U1.7 65.58,43.64 65.41,43.81 C46.1 65.39,44.45 64.77,44.45 59.69,49.53 JP38.3 46.99,49.53 43.18,45.72 JP18.1 JP17.1
  Bottom 0.254: JP17.1 C41.+
P0.26
  Top 0.254: JP19.1 JP20.1 45.72,53.34 46.99,52.07 JP38.4 59.69,52.07 64.39,47.37 64.26,45.59 64.77,45.09 66.17,45.09 C47.1 67.1,44.14 U1.6
  Bottom 0.254: JP19.1 C42.+
P0.27
  Top 0.127: U1.25 65.37,34.64 65.02,34.29 JP37.1
P0.28
  Top 0.127: U1.24 55.92,35.14 54.23,36.83 JP37.2
P0.29
  Top 0.127: JP35.3 57.15,13.97 64.77,21.59 71.12,21.59 72.01,22.48 72.01,31.75 71.7,32.06 U1.29
P0.30
  Top 0.127: JP35.2 59.69,13.97 66.04,20.32 71.12,20.32 72.33,21.53 72.33,32.19 72.26,32.26 72.26,32.98 U1.30
P1.0
  Top 0.127: JP46.3 57.15,67.31 72.64,51.69 72.64,48.3 U1.95 72.77,48.31 72.77,48.13 72.64,48.39
P1.1
  Top 0.127: U1.94 73.2,53.8 59.69,67.31 JP46.4
P1.4
  Top 0.127: U1.93 73.7,55.84 62.23,67.31 JP46.5
P1.8
  Top 0.127: U1.92 74.2,57.88 64.77,67.31 JP45.1
P1.9
  Top 0.127: U1.91 74.7,59.92 67.31,67.31 JP45.2
P1.10
  Top 0.127: U1.90 75.2,61.96 69.85,67.31 JP45.3
P1.14
  Top 0.127: U1.89 75.7,64 72.39,67.31 JP45.4
P1.15
  Top 0.127: U1.88 76.2,66.04 74.93,67.31 JP45.5
P1.16
  Top 0.127: U1.87 76.7,66.54 77.47,67.31 JP44.1
P1.17
  Top 0.127: U1.86 77.2,64.5 80.01,67.31 JP44.2
P1.18
  Top 0.127: JP35.1 62.23,13.97 67.31,19.05 72.39,19.05 73.2,19.86 U1.32
P1.19
  Top 0.127: U1.33 73.7,19.09 72.39,17.78 68.58,17.78 64.77,13.97 JP36.5
P1.20
  Top 0.127: JP36.4 67.31,13.97 69.85,16.51 73.66,16.51 74.2,17.05 U1.34
P1.21
  Top 0.127: JP36.3 69.85,13.97 71.12,15.24 73.66,15.24 74.7,16.28 U1.35
P1.22
  Top 0.127: 72.39,13.97 JP36.2 75.2,15.51 U1.36
P1.23
  Top 0.127: U1.37 75.7,14.74 74.93,13.97 JP36.1
P1.24
  Top 0.127: JP33.5 77.47,13.97 76.2,15.24 U1.38
P1.25
  Top 0.127: JP33.4 80.01,13.97 76.7,17.28 U1.39
P1.26
  Top 0.127: JP33.3 82.55,13.97 77.2,19.32 U1.40
P1.27
  Top 0.127: JP33.2 85.09,13.97 78.7,20.36 78.7,28.79 78.99,28.96 78.99,32 78.7,32.17 U1.43
P1.28  (via drill 0.51)
  Top 0.127: U1.44 79.2,34.75 v80.14,38.1 | v115.57,38.1 116.08,38.1
  Top 0.254: 116.08,38.1 125.86,38.1 128.78,41.02 128.78,45.97 JP28.1
  Bottom 0.127: v80.14,38.1 v115.57,38.1
P1.29
  Top 0.127: JP33.1 87.63,13.97 79.7,21.9 U1.45
P1.30
  Top 0.254: U1.21 65.2,36.64 C22.1 57.55,37.7 55.88,39.37 JP37.3 49.53,39.37 47.24,37.08 47.24,29.21 36.7,18.67 36.7,13.97 35.56,12.83 34.42,12.83 JP9.1 JP8.1
  Bottom 0.254: JP8.1 38.12,8.89 C23.+
P1.31
  Top 0.127: 34.29,20.19 JP11.1
  Top 0.254: JP10.1 34.29,20.19 34.54,20.45 35.31,20.45 36.96,22.1 36.83,23.88 44.58,31.62 44.58,36.96 49.53,41.91 JP37.4 55.12,41.91 58.67,38.35 65.41,38.35 66.06,37.7 C43.1 67.24,37.14 U1.20
  Bottom 0.254: JP10.1 C38.+
P2.0
  Top 0.127: U1.75 84.74,46.64 86.36,48.26 86.36,49.53 101.6,64.77 JP42.1 | JP42.1 104.14,64.77 | JP30.2 107.95,16.51 106.68,17.78 106.68,63.5 105.41,64.77 JP42.1
P2.1
  Top 0.127: U1.74 85.51,46.14 101.6,62.23 JP42.2 104.14,62.23 105.41,60.96 105.41,15.24 109.22,11.43 JP29.2
P2.2
  Top 0.127: JP42.3 101.6,59.69 87.8,45.89 87.34,45.85 84.96,45.85 84.76,45.64 U1.73
P2.3
  Top 0.127: U1.70 88.59,44.14 101.6,57.15 JP42.4
P2.4
  Top 0.127: U1.69 90.63,43.64 101.6,54.61 JP42.5
P2.5
  Top 0.127: U1.68 92.67,43.14 101.6,52.07 JP41.1
P2.6
  Top 0.127: U1.67 94.71,42.64 101.6,49.53 JP41.2
P2.7
  Top 0.127: U1.66 96.75,42.14 101.6,46.99 JP41.3
P2.8
  Top 0.127: U1.65 98.79,41.64 101.6,44.45 JP41.4
P2.9
  Top 0.127: U1.64 100.83,41.14 101.6,41.91 JP41.5
P2.10  (via drill 0.51)
  Top 0.127: S2.B 117.3,112.22 115.57,110.49 114.62,110.49 R4.1 | U1.53 81.36,35.64 v80.9,35.56 | v111.63,35.56 111.63,84.96 v114.3,88.9
  Top 0.508: v114.3,107.95 R4.1
  Bottom 0.127: v80.9,35.56 v111.63,35.56
  Bottom 1.016: v114.3,88.9 v114.3,107.95
P2.11
  Top 0.127: U1.52 85.51,35.14 101.6,19.05 JP39.4
P2.12
  Top 0.127: U1.51 84.74,34.64 86.36,33.02 86.36,31.75 101.6,16.51 JP39.5
P2.13
  Top 0.127: U1.50 82.2,32.1 100.33,13.97 JP34.1
P3.25
  Top 0.127: JP35.4 54.61,13.97 63.5,22.86 69.85,22.86 70.48,23.5 70.48,31.75 70.7,31.96 U1.27
P3.26
  Top 0.127: JP35.5 52.07,13.97 62.23,24.13 69.85,24.13 70.2,24.48 U1.26
P4.28
  Top 0.127: JP44.4 85.09,67.31 79.2,61.42 79.25,61.37 79.25,52.45 79.38,52.32 79.38,49.4 79.2,49.23 U1.82
P4.29
  Top 0.127: JP44.3 82.55,67.31 77.7,62.46 77.72,62.44 77.72,56.52 77.47,56.26 77.47,49.4 77.7,49.17 U1.85
RESET_N  (via drill 0.51)
  Top 0.127: S1.B 90.17,117.65 R3.1 87.94,112.71 86.11,110.87 85.15,110.87 C14.1 84.01,110.81 81.28,108.08 | JP47.2 72.39,107.95 73.66,106.68 80.01,106.68 81.28,107.95 81.28,108.08 | U1.17 76.17,38.64 76.2,38.61 76.71,38.61 78.74,40.64 v80.01,40.64 | v110.49,40.64 110.49,87.76 106.81,91.44 91.44,91.44 87.63,95.25 87.63,106.3 85.98,107.95 81.41,107.95 81.28,108.08
  Bottom 0.127: v80.01,40.64 v110.49,40.64
RTCK  (via drill 0.51)
  Top 0.127: U1.100 70.2,47.15 70.61,46.74 73.91,46.74 v74.42,46.23 | v65.79,83.69 65.79,99.31 62.87,101.85 R15.2 62.8,109.6 61.72,109.6 61.47,109.86 v60.96,109.86
  Bottom 0.127: v74.42,46.23 74.42,63.63 70.99,67.06 70.99,78.49 v65.79,83.69 | v60.96,109.86 X4.11
TCK  (via drill 0.51)
  Top 0.127: v63.5,82.55 63.5,97.79 59.18,101.6 R14.2 57.59,109.54 v57.15,109.98 | U1.5 69.66,44.64 71.12,43.18 v73.53,43.18
  Bottom 0.127: v73.53,43.18 73.53,62.36 68.58,67.31 68.58,70.48 68.45,70.61 68.45,77.6 v63.5,82.55 | X4.9 58.42,115.57 57.15,114.3 v57.15,109.98
TDI  (via drill 0.51)
  Top 0.127: v58.42,80.01 58.42,92.71 50.8,100.33 R11.1 50.86,109.6 51.82,109.6 52.45,110.24 v52.45,110.87 | U1.2 70.06,46.14 70.61,45.59 v72.01,45.59
  Bottom 0.127: v72.01,45.59 72.01,58.8 63.5,67.31 63.5,74.93 v58.42,80.01 | X4.5 53.34,115.57 52.45,114.68 v52.45,110.87
TDO  (via drill 0.51)
  Top 0.127: v68.58,85.09 68.58,101.47 64.77,105.28 R13.1 64.84,109.47 66.04,109.47 66.8,110.24 v66.8,110.49 | U1.1 70.2,46.64 70.48,46.35 73.15,46.35 74.17,45.34 v75.31,45.34
  Bottom 0.127: v75.31,45.34 75.31,64.39 73.66,66.04 73.66,80.01 v68.58,85.09 | X4.13 66.04,114.3 v66.8,110.49
TMS  (via drill 0.51)
  Top 0.127: v60.96,81.28 60.96,95.25 54.1,101.73 R12.1 54.16,109.6 55.12,109.6 55.75,110.24 v55.75,110.87 | U1.3 70.06,45.64 70.61,45.09 71.5,45.09 71.88,44.58 v72.64,44.58
  Bottom 0.127: v72.64,44.58 72.9,60.58 66.04,67.44 66.04,76.2 v60.96,81.28 | X4.7 55.88,111 v55.75,110.87
TRST_N  (via drill 0.51)
  Top 0.127: 67.89,45.14 U1.4 70.18,45.14 v70.99,44.32 | v55.88,78.74 55.88,91.44 46.99,100.33 46.99,109.22 | R9.1 46.99,109.6 48.51,109.6 49.02,110.11 v49.02,110.62
  Top 0.254: 46.99,109.22 R9.1
  Bottom 0.127: v70.99,44.32 70.99,57.28 60.83,67.44 60.83,73.91 60.71,73.91 v55.88,78.74 | X4.3 50.8,116.71 49.02,114.94 v49.02,110.62
VBAT  (via drill 0.51)
  Top 0.254: U1.19 73.61,37.64 v73.66,37.59 | v50.8,81.28 50.8,85.09 52.83,87.12 52.83,90.42 52.7,90.55 51.69,90.55 JP4.4
  Bottom 0.127: C32.1 65.19,54.98 C33.+
  Bottom 0.254: v73.66,37.59 73.66,40.51 69.09,45.09 69.09,52.58 | 69.09,52.58 69.09,56.52 58.42,67.18 58.42,73.66 v50.8,81.28 | C32.1 68.95,52.44 69.09,52.58
VDD_3V3  (via drill 0.51)
  Top 0.127: U1.71 81.98,44.64 81.41,44.07 | 81.41,39.37 81.41,36.7 81.92,36.2 83.75,36.2 U1.54 83.86,36.2 84.96,36.2 85.09,36.32 C25.1 | 81.41,39.37 81.41,43.18 | 81.41,43.18 81.41,44.07 | 81.41,44.07 77.72,44.07 76.96,44.83 76.96,46.48 76.45,46.99 72.39,46.99 72.2,47.18 U1.96 72.26,48.3 | U1.71 82.74,44.64 | 81.41,39.37 81.28,39.24 78.61,39.24 71.12,34.29 71.12,33.12 U1.28 | 81.41,43.18 v81.28,43.18 | U1.71 83.86,44.58 85.09,44.58 85.34,44.83 C26.1
  Top 0.254: 115.32,42.55 116.23,42.55 C28.+ | 72.26,48.3 72.26,51.44 70.61,53.09 C27.1 | C24.1 71.25,32.99 U1.28
  Top 0.508: 116.84,72.39 JP27.2 113.03,68.96 v113.03,43.18 114.68,43.18 115.32,42.55 | C28.+ C15.+
  Bottom 0.508: v81.28,43.18 v113.03,43.18
VDD_DCDC_3V3  (via drill 0.51)
  Top 0.127: v78.23,45.72 78.2,45.75 | C30.1 78.11,32.95 U1.42 | C29.1 78.23,48.27 U1.84
  Top 0.254: U1.42 78.23,33.07 v78.23,36.07 | 78.2,45.75 U1.84 | 116.23,46.99 C31.+
  Top 0.508: v114.3,45.72 114.3,46.99 | 116.84,66.04 JP26.2 114.3,63.5 114.3,46.99 | 114.3,46.99 116.23,46.99 | C31.+ C21.+
  Bottom 0.508: v78.23,36.07 v78.23,45.72 v114.3,45.72
VDDA  (via drill 0.51)
  Top 0.127: 68.58,42.16 U1.10 | C35.+ 37.44,78 38.35,77.09 39.37,77.09
  Top 0.254: v70.1,42.16 68.62,42.16 U1.10 | 68.58,42.16 66.44,42.16 C34.1
  Top 0.508: v39.37,74.93 39.37,77.09 JP48.2 36.83,85.09 36.83,90.17 JP6.4
  Bottom 0.254: 69.85,42.16 v70.1,42.16 69.72,42.55 69.72,43.18 66.04,46.86 66.04,49.91 42.8,73.15 39.75,74.55 v39.37,74.93
VREF  (via drill 0.51)
  Top 0.127: C36.1 67.31,40.64 67.69,41.02 68.97,41.02 69.09,41.14 | C37.+ 22.86,71.48 22.48,71.1
  Top 0.254: U1.12 69.09,41.14 71.25,41.14 v72.26,40.13
  Top 0.508: R5.3 11.59,40.64 5.08,40.64 2.54,43.18 2.54,72.39 3.81,73.66 12.7,73.66 14.15,72.21 R6.3 22.48,71.1 39.86,71.1 42.04,73.28 42.04,74.3 42.29,74.55 v41.91,74.93 JP48.1 41.91,83.82 43.18,85.09 45.47,85.09 46.23,85.85 46.23,88.01 45.85,88.39 45.85,90.04 JP5.4
  Bottom 0.254: v72.26,40.13 72.26,41.02 66.8,46.86 66.8,50.93 63.5,54.23 47.12,70.74 44.83,73.28 43.18,74.93 v41.91,74.93 41.66,74.68

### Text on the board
Bottom: 08-20-2010
tPlace: JTAG | Reset | ISP | AGND | AGND | EXT VDDA | JP4 - VBAT | 3 - 4: connected to +3V3 | USB Power | 4(+VBat) & 2(GND): connect ext. battery | + | JP5 - VREF | 3 - 4: Ext. VRef | 2 - 4: connected to +3V3 | JP3 - VDD | GND | 1 - 2: USB connector | JP6 - VDDA | 1 - 3: Ext. VDD | 3 - 4: connected to +3V3 | 2 - 4: Ext. VDDA | GND | AGND | EXT VREF | POT2 | POT2 | AD0.7 | BNC2 | P2.0 | BNC2 | P0.2 | P1.0 | P1.1 | P1.4 | P1.9 | P0.4 | P0.9 | P0.3 | P1.14 | P0.5 | P0.6 | P0.7 | P0.8 | P2.1 | POT2 | P1.8 | P1.10 | P1.15 | P1.16 | P1.17 | P4.29 | P4.28 | P2.2 | AD0.6 | BNC2 | P2.3 | EXT VDD3V3 | P2.4 | POT2 | P0.26 | AD0.3 | P2.5 | BNC2 | P0.25 | P2.6 | COM0 | + | POT2 | P0.24 | P2.7 | P0.23 | P2.8 | AD0.2 | BNC2 | P1.31 | P2.9 | P1.30 | P0.16 | POT1 | POT1 | P0.28 | P0.15 | P0.27 | P0.17 | AD0.1 | JP31 & JP32 ON -> UART0 | BNC1 | BNC1 | P0.18 | JP29 & JP30 ON -> UART1 | LPC1768 | P0.19 | POT1 | P0.20 | AD0.0 | BNC1 | P0.21 | P0.22 | POT1 | P2.11 | AD0.5 | BNC1 | P1.18 | P1.23 | P1.29 | P2.12 | P3.26 | P3.25 | P0.29 | P0.30 | P1.19 | P1.20 | P1.21 | P1.22 | P1.24 | P1.25 | P1.26 | P1.27 | P0.0 | P0.1 | P0.10 | P0.11 | P2.13 | POT1 | AD0.4 | BNC1 | LPC1768 ADC board | Rev. B | Serial # | NXP Semiconductors USA Inc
